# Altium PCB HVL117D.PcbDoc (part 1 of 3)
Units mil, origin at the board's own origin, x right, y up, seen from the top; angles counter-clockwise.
Board outline 2004.03 x 2004.03 mil, 6 copper layers (Top Layer, InternalPlane1, MidLayer1, InternalPlane2, MidLayer2, Bottom Layer), stack 60.56 mil thick; 218 components, 157 nets, 658 pads, 273 vias.
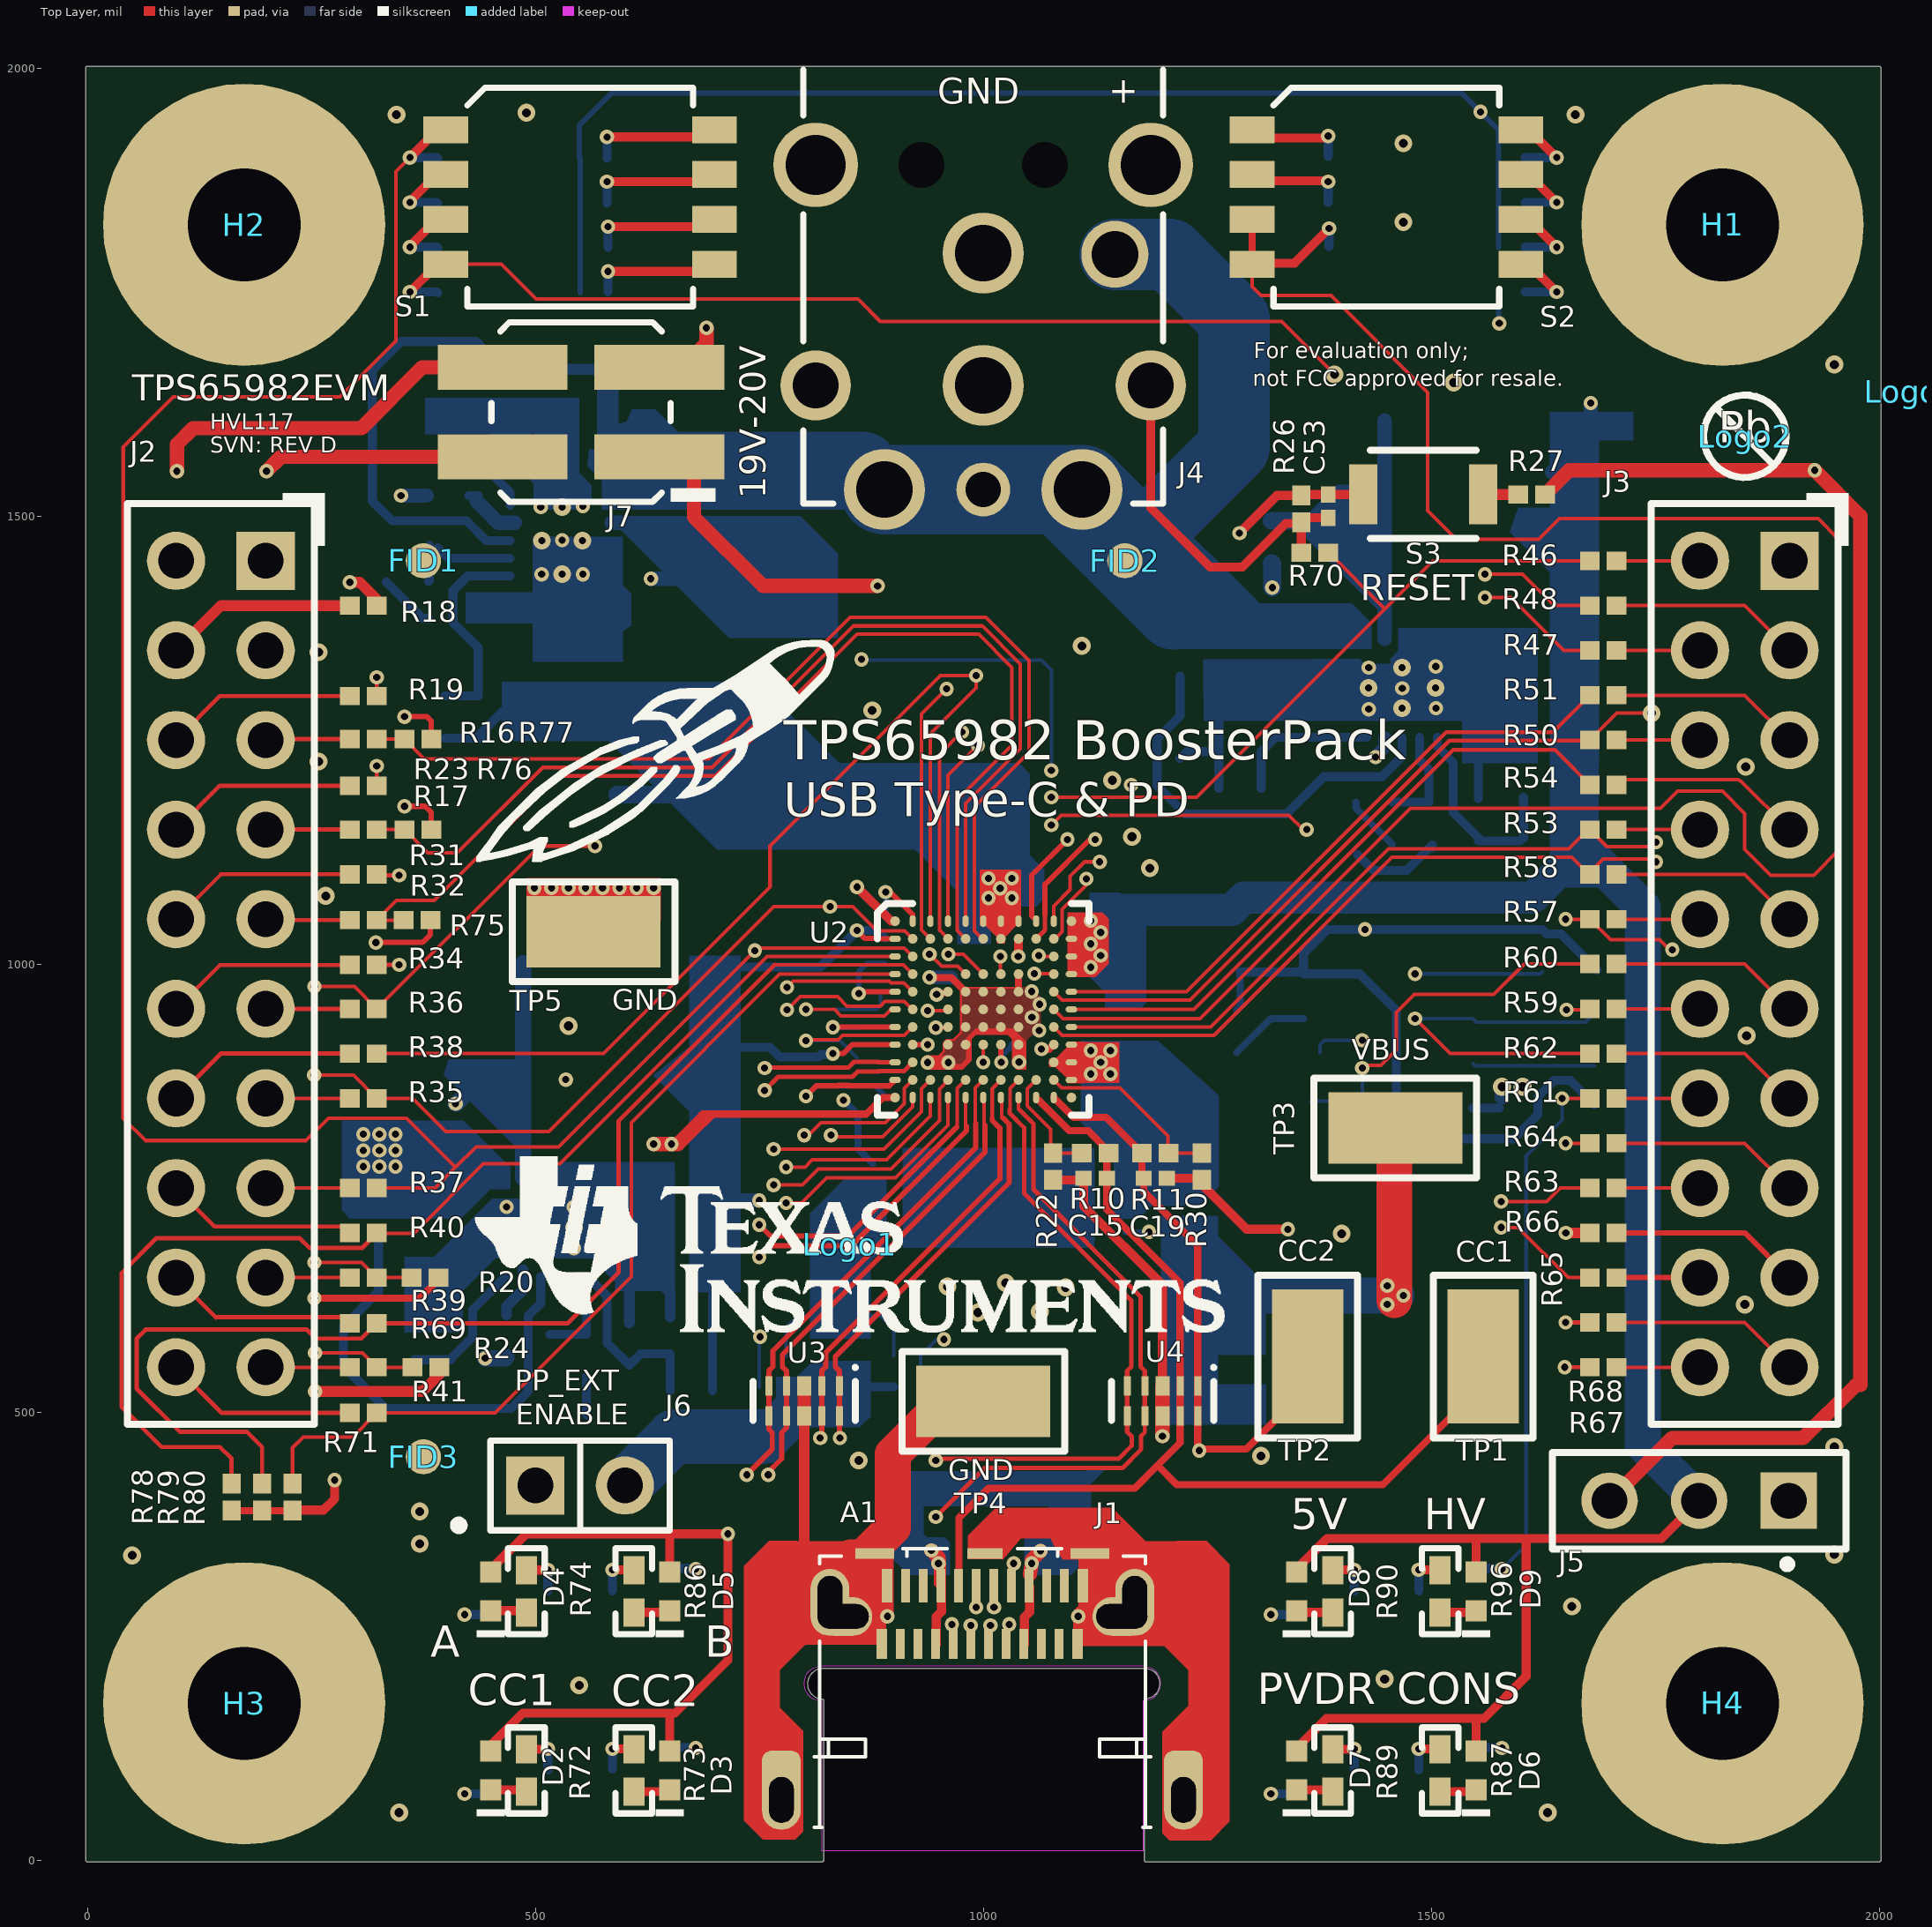
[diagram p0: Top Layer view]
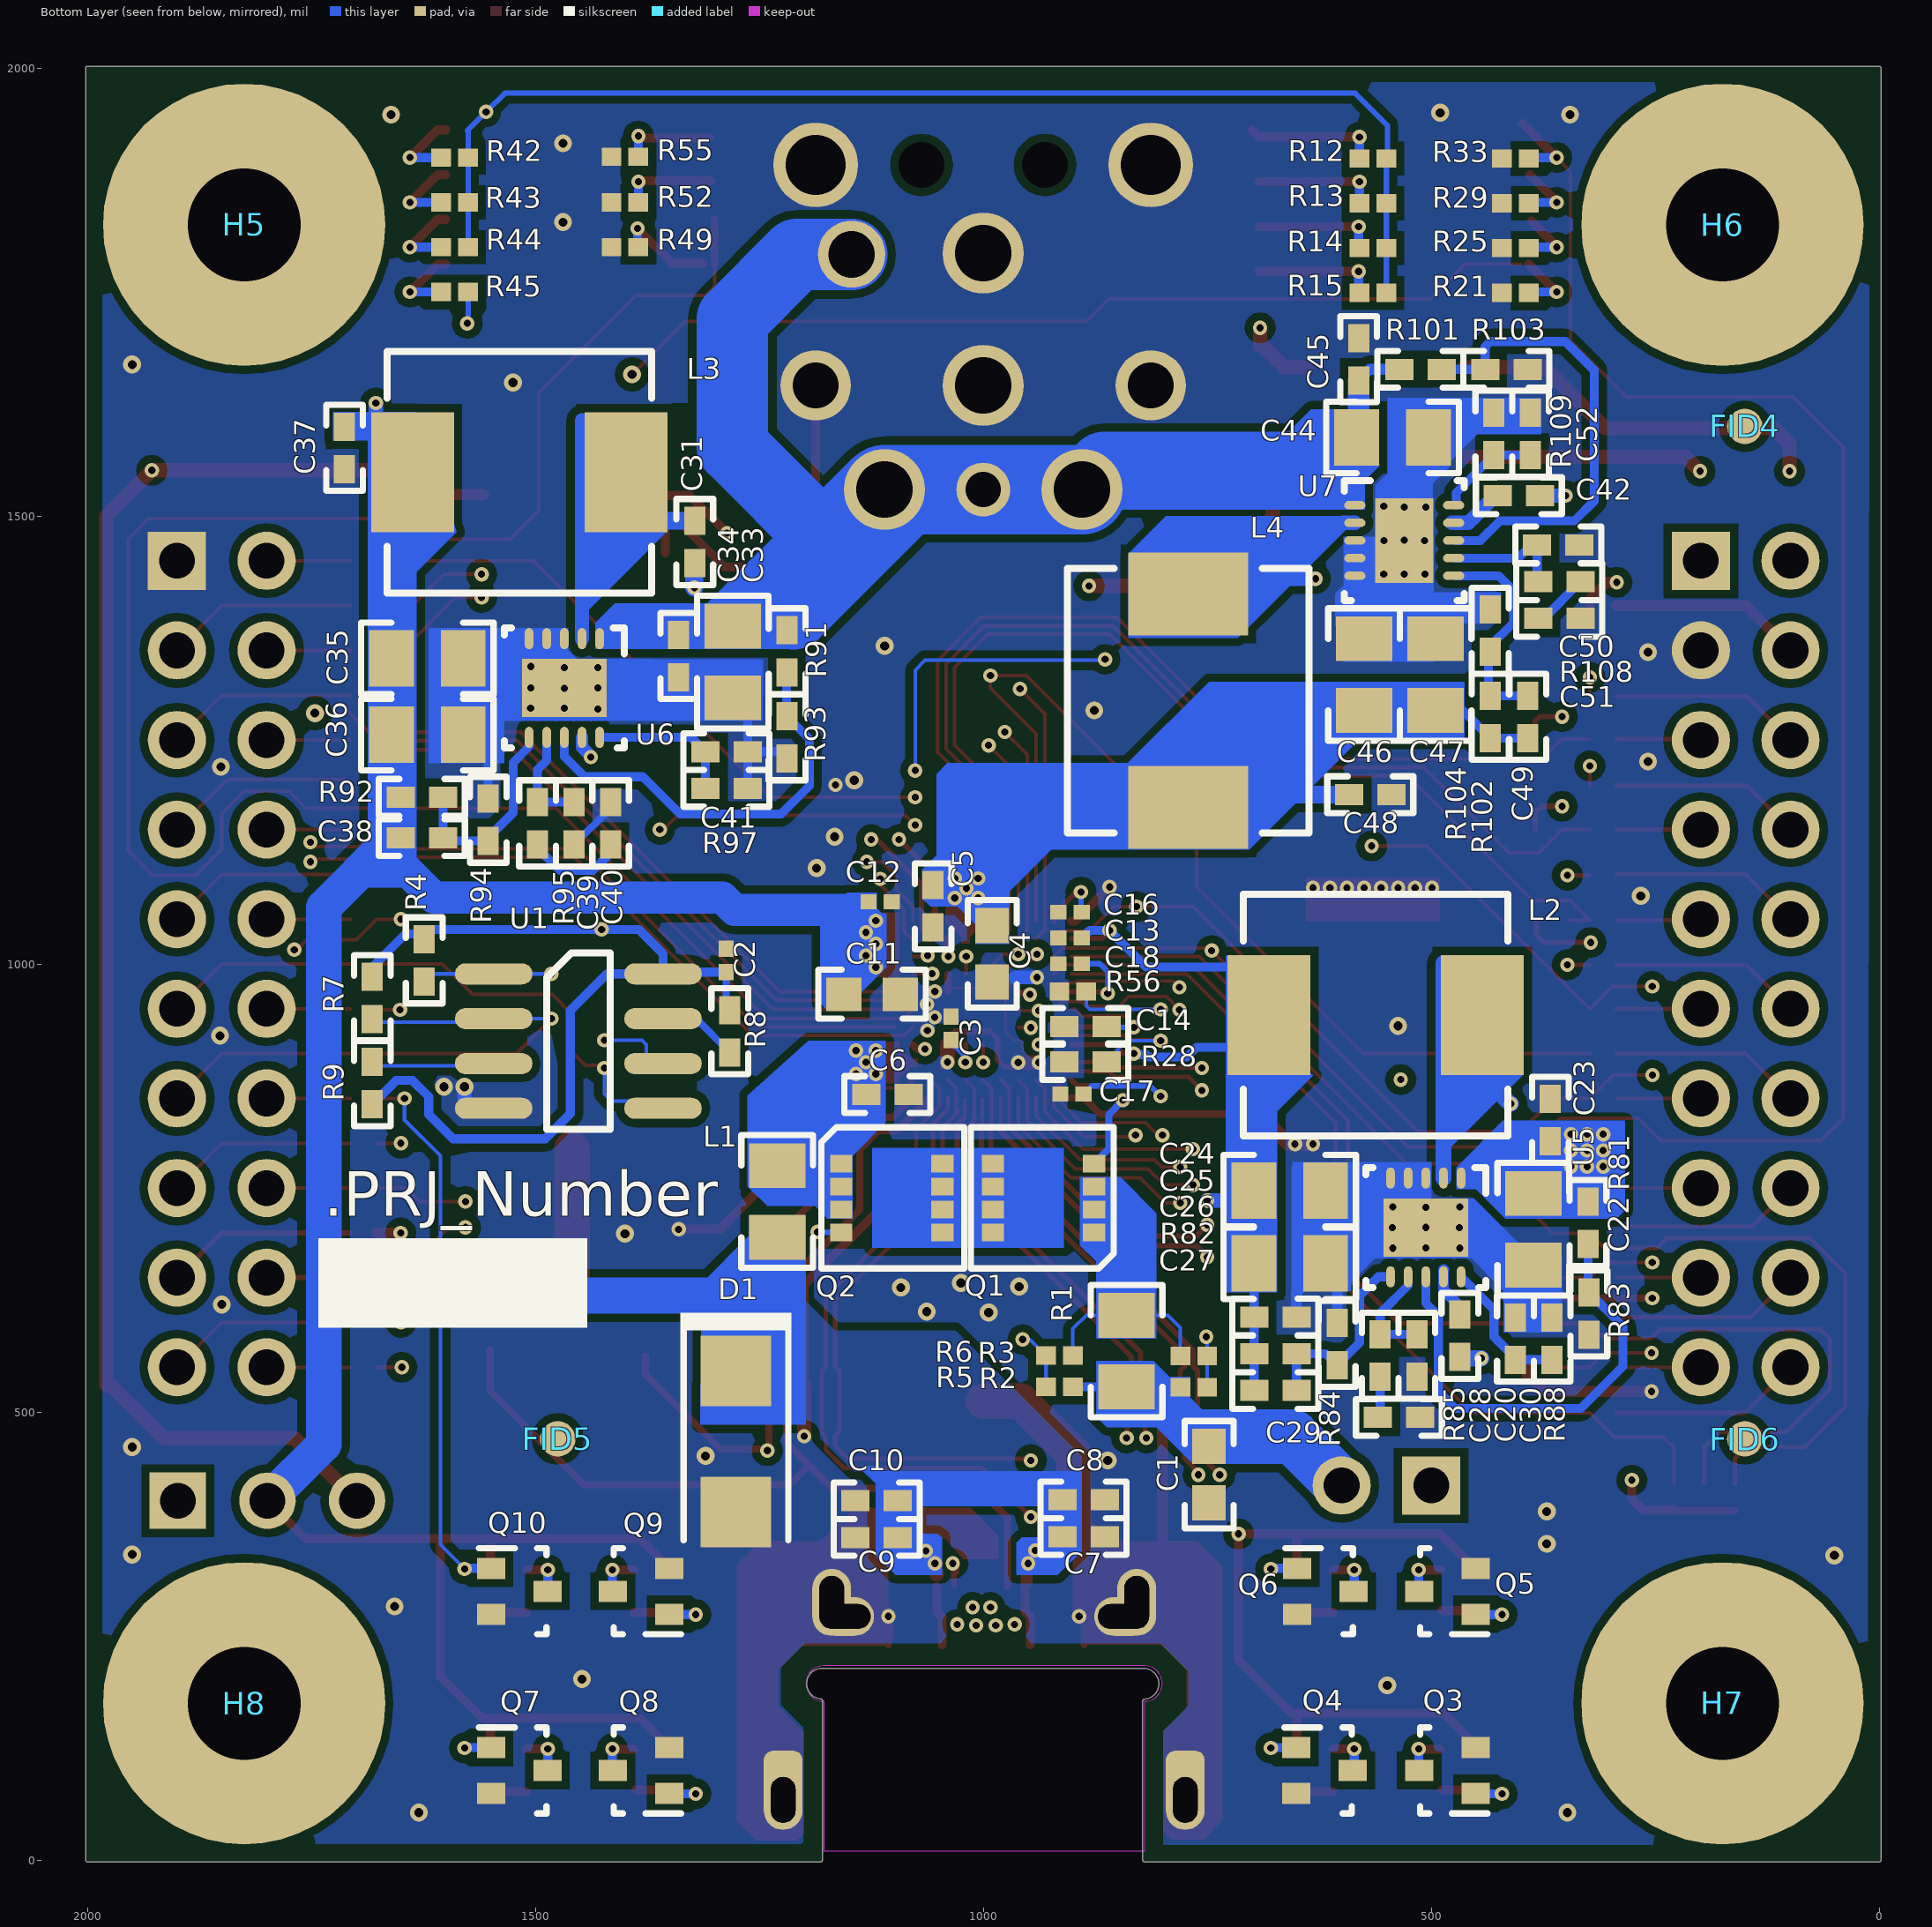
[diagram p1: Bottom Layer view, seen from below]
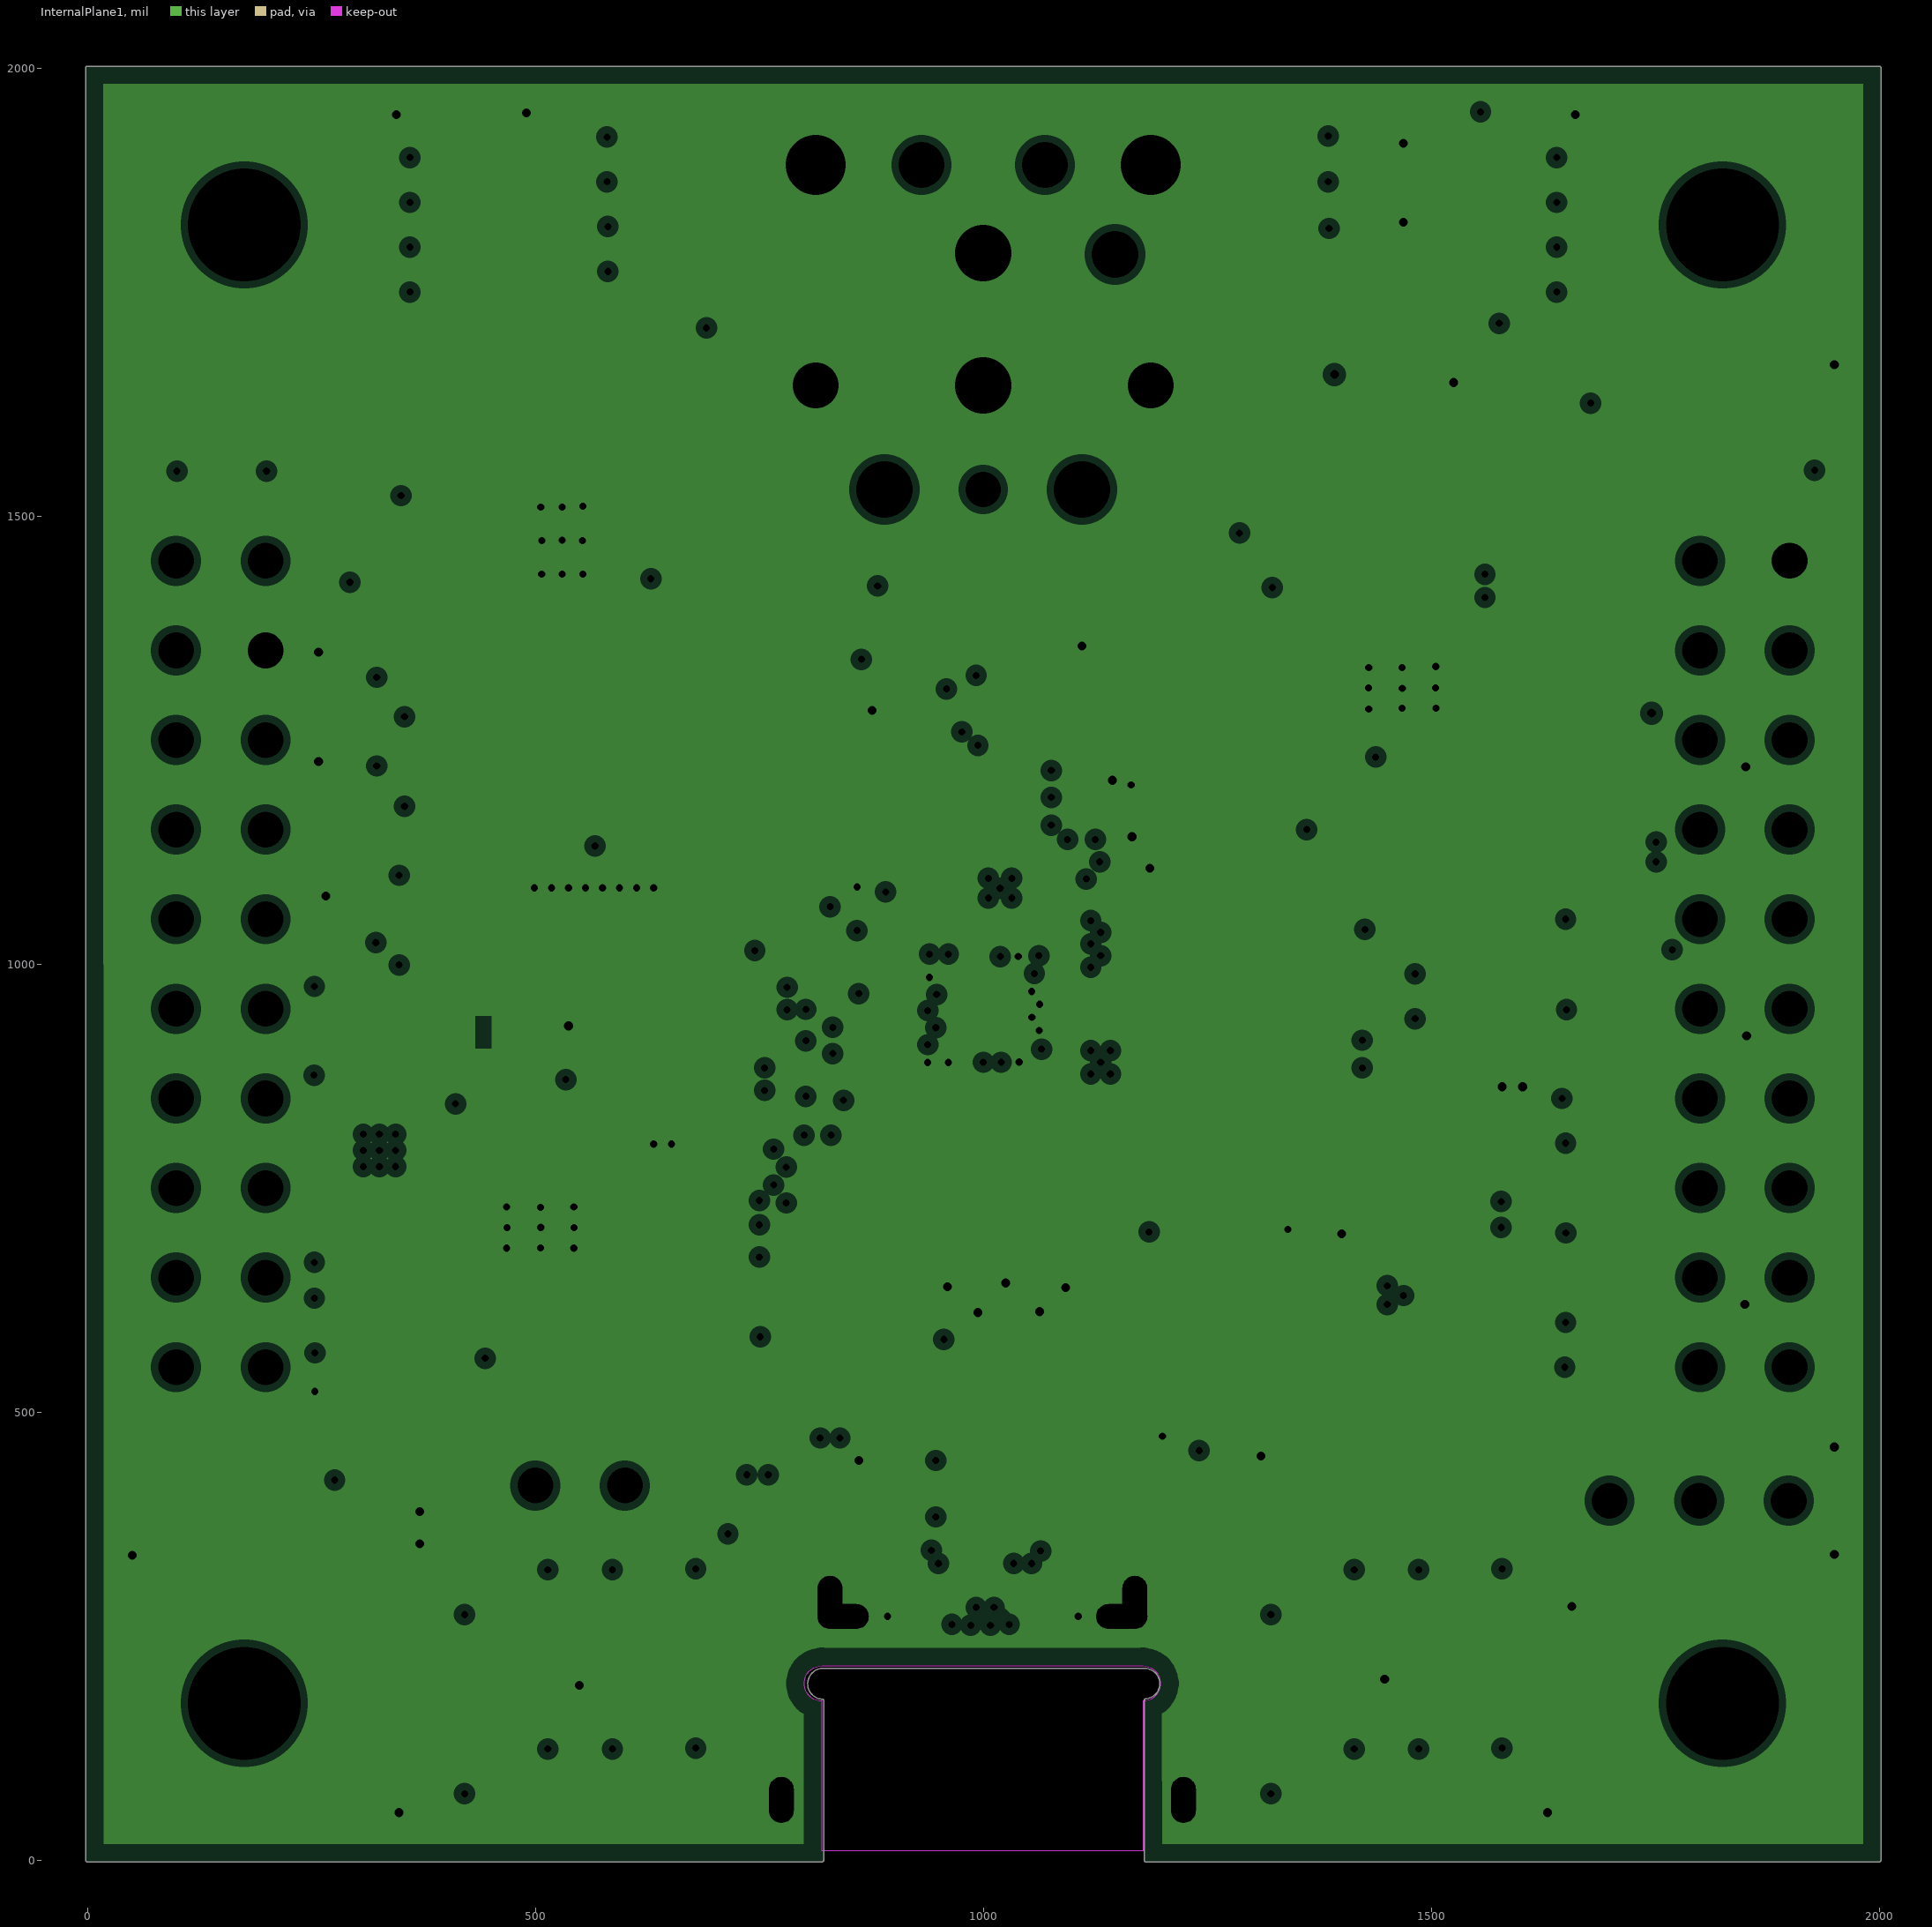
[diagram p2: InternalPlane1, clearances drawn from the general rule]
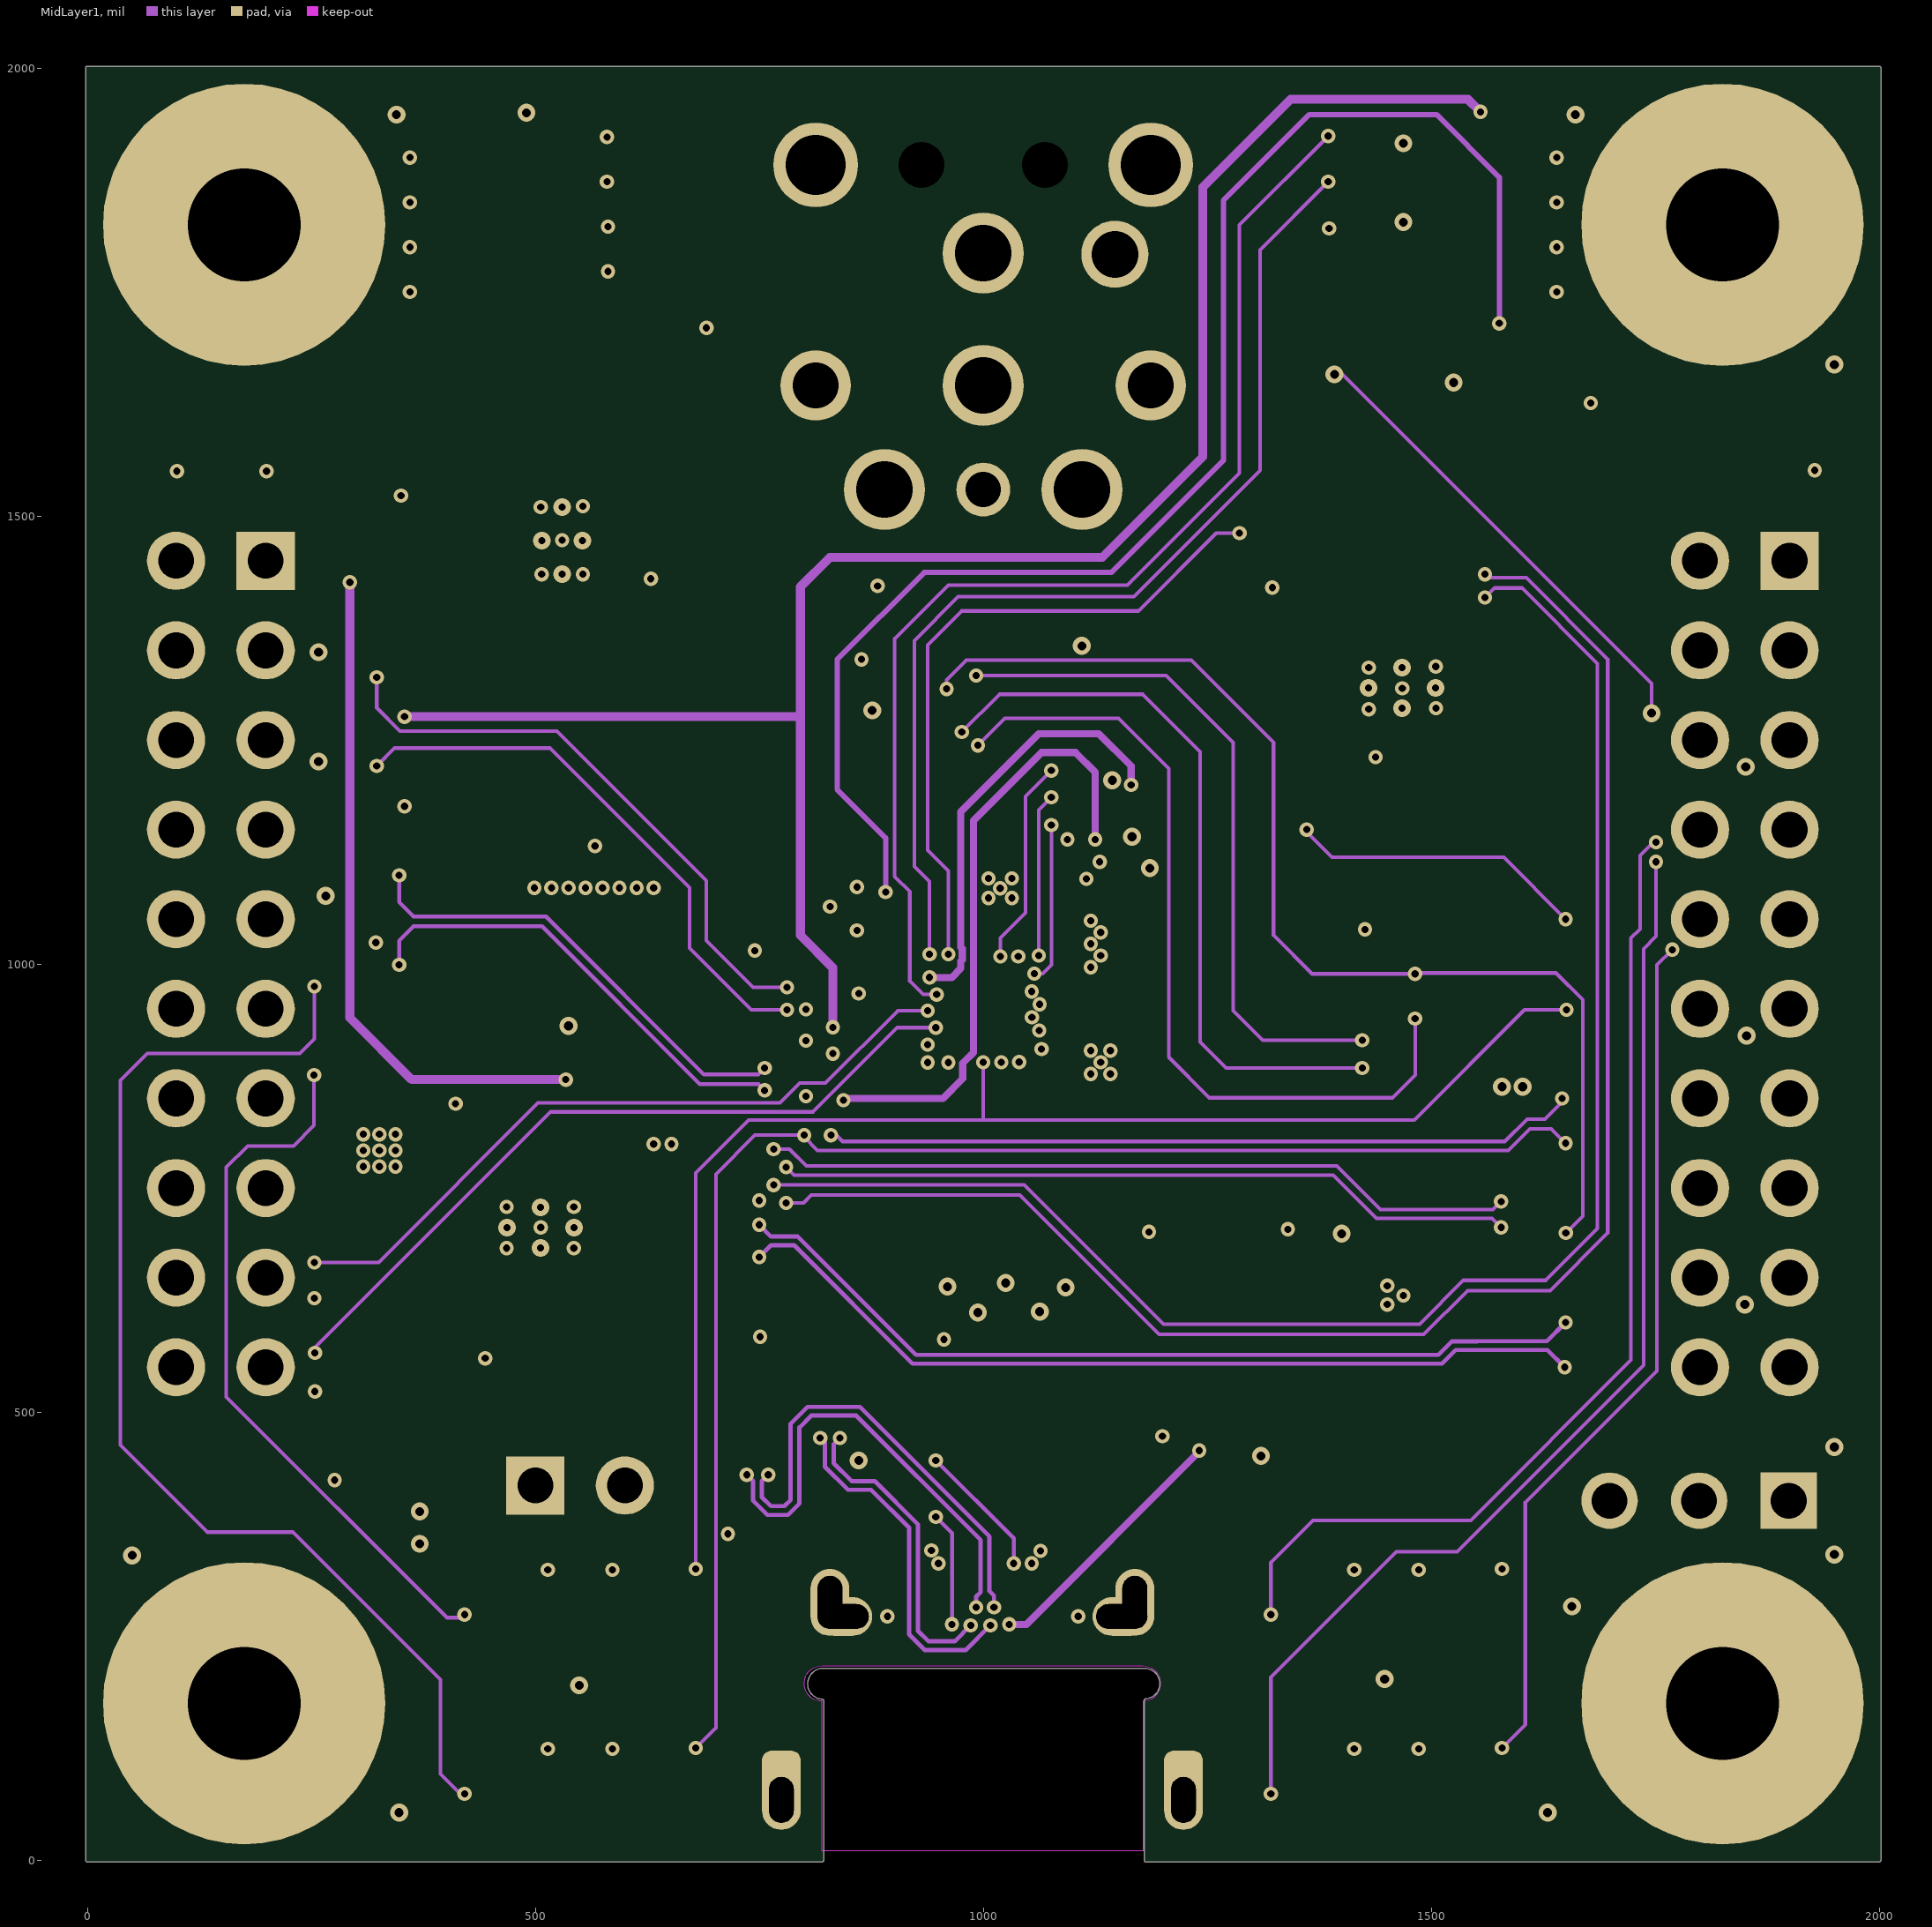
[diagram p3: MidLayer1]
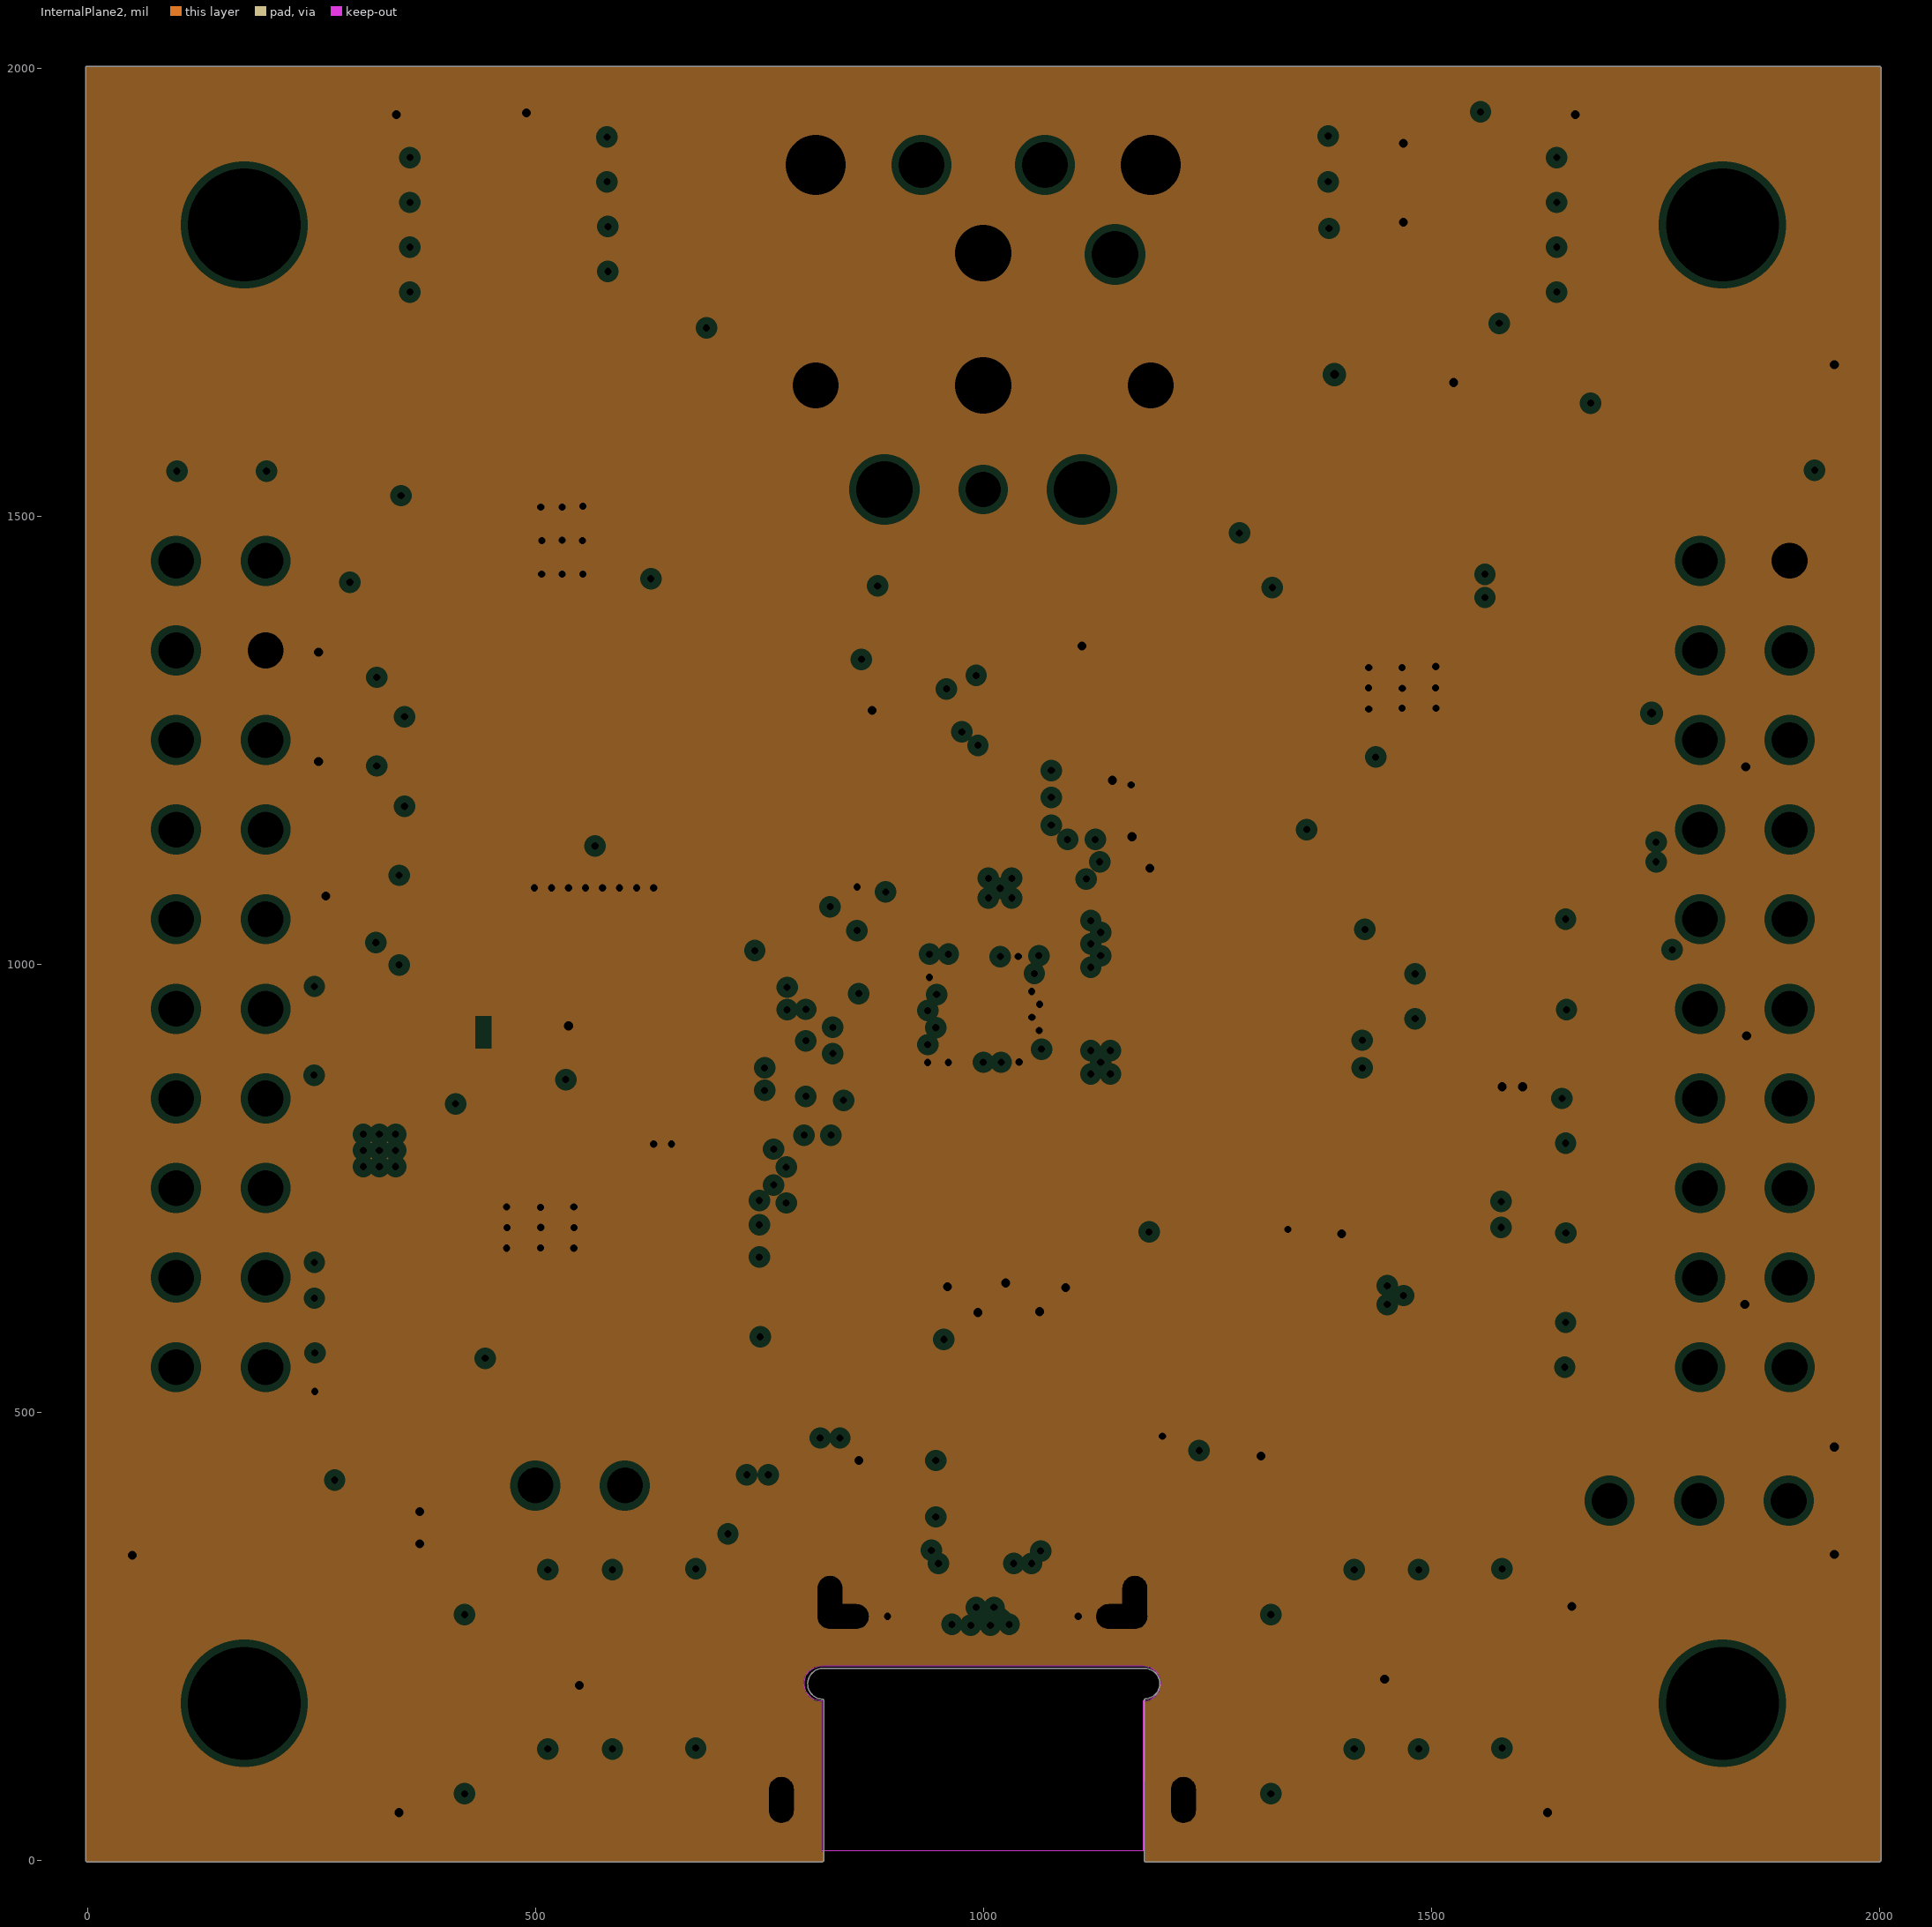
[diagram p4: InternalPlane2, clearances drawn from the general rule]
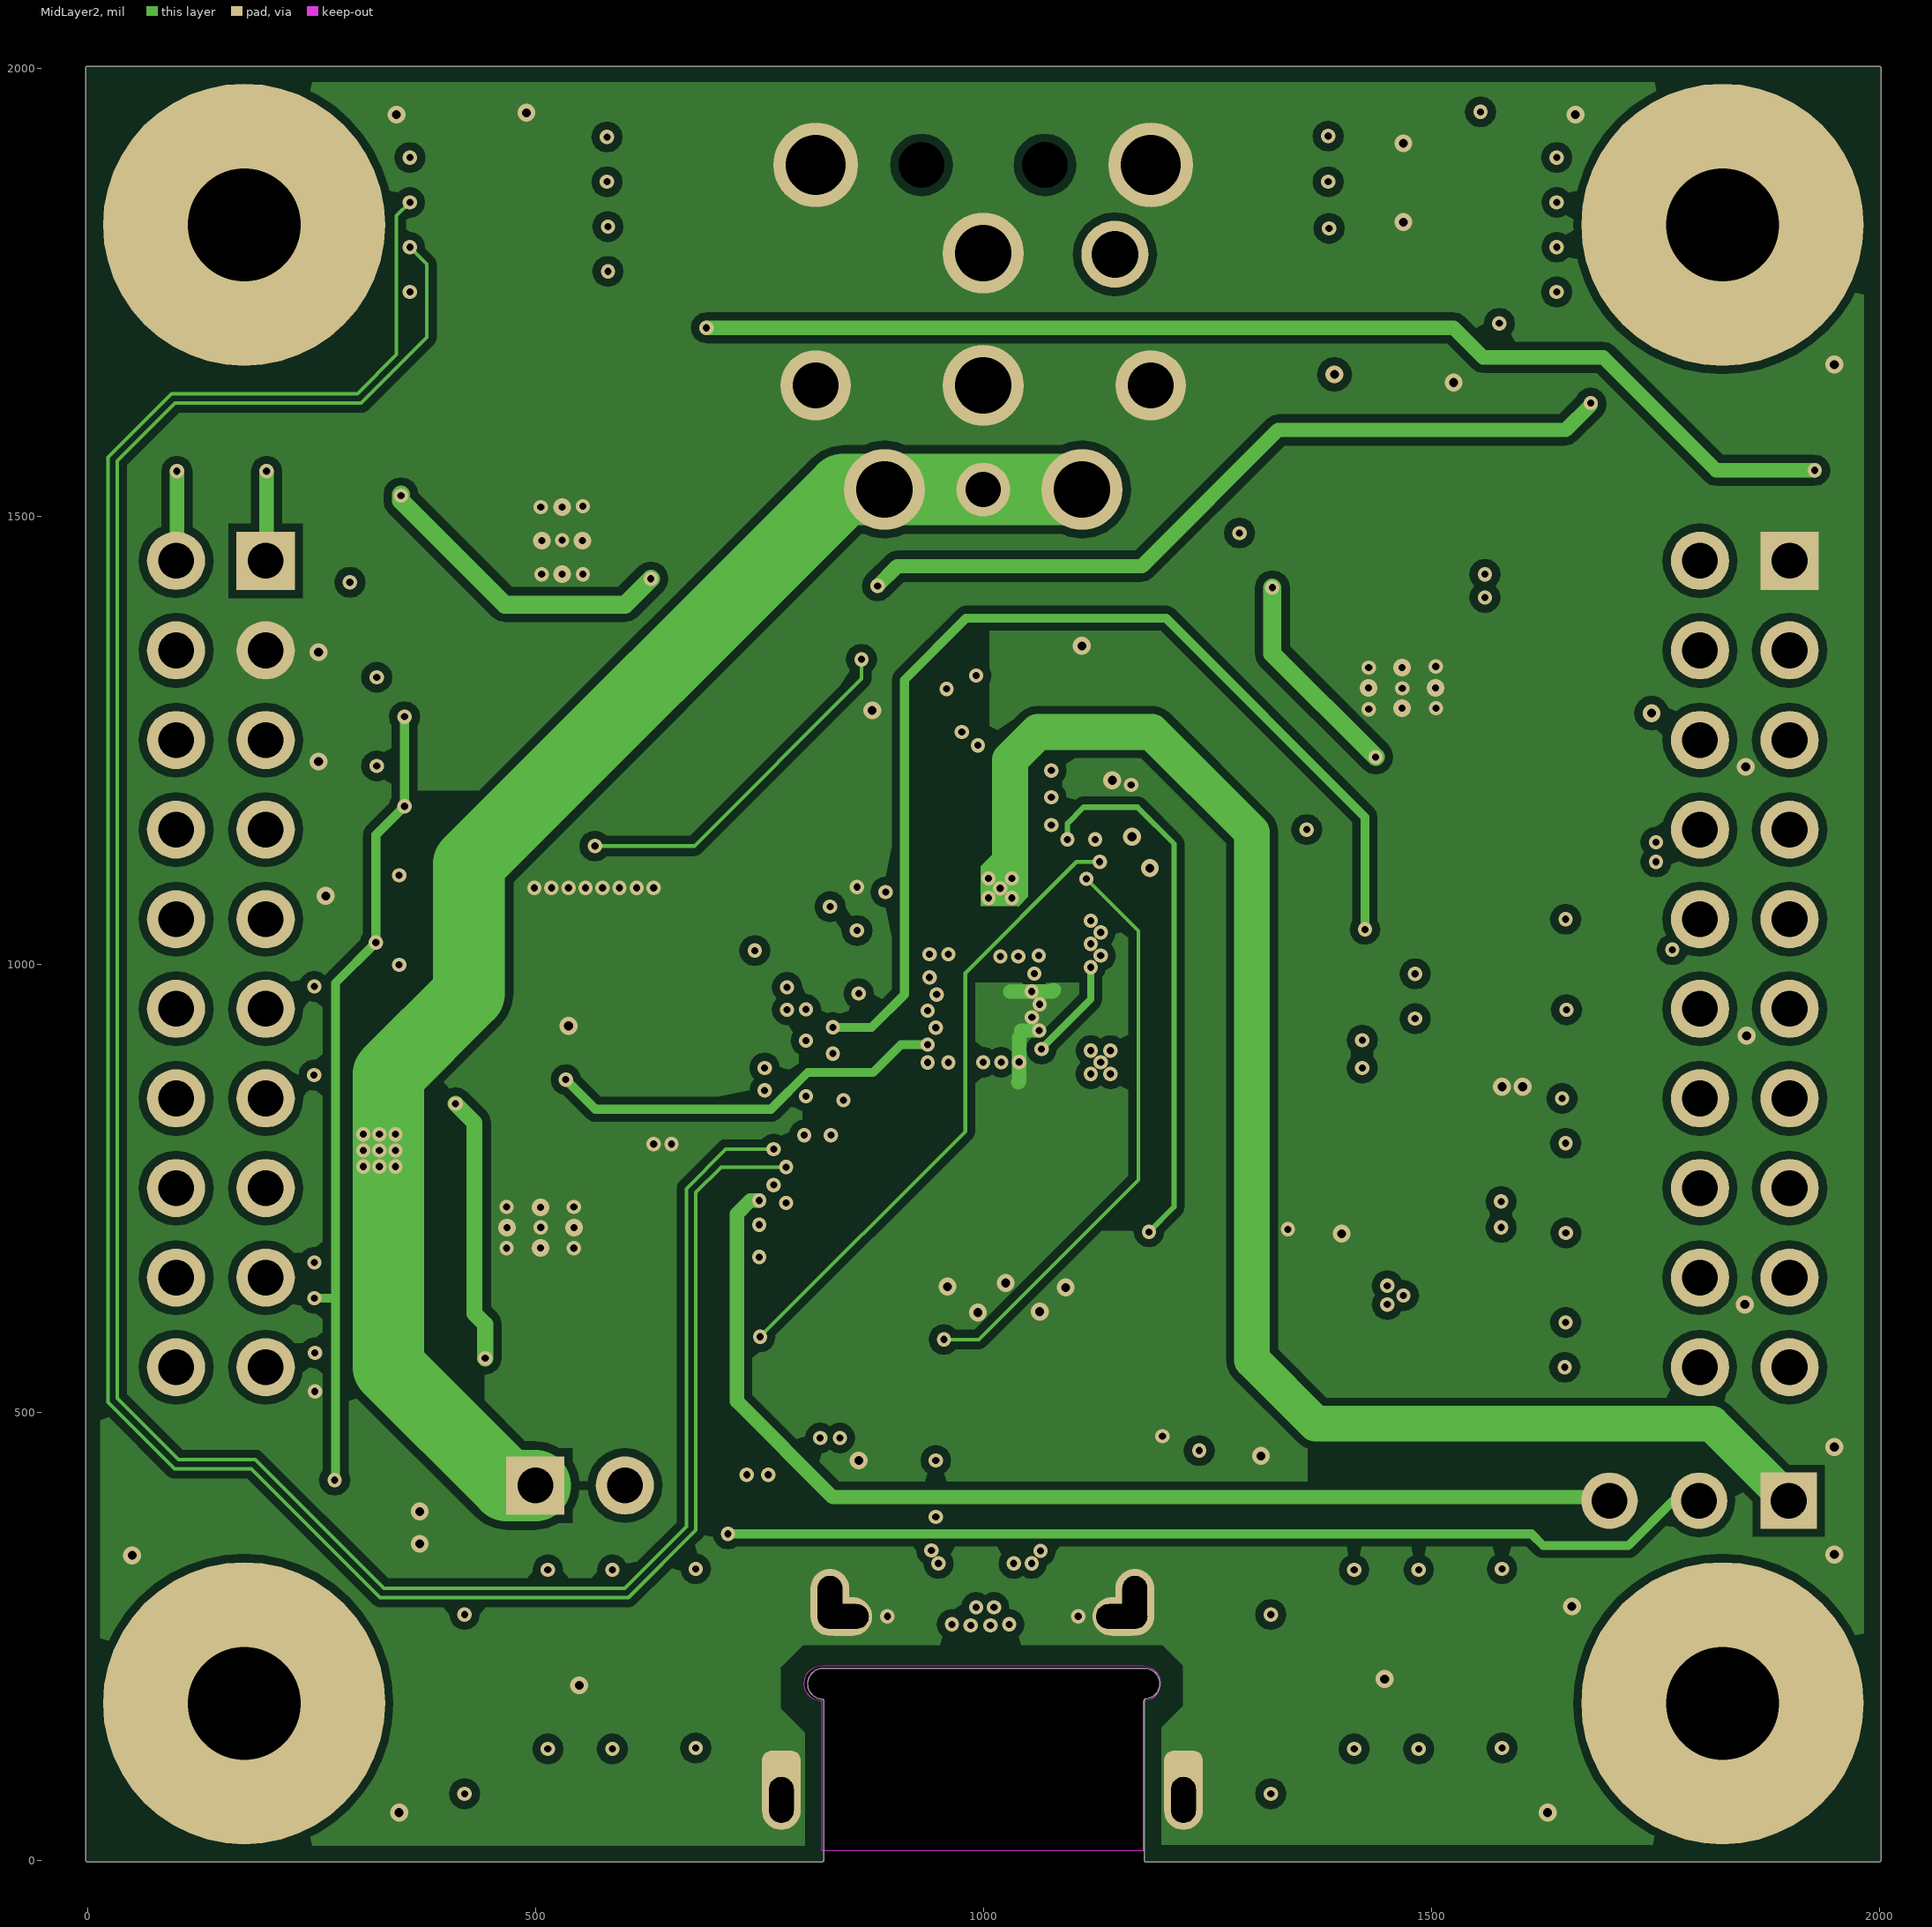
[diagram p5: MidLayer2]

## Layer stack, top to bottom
Top Layer: signal copper 1.4
Dielectric: core 5.91, FR-4, Dk 4.1
InternalPlane1: plane copper 1.4, net GND
Dielectric: prepreg 7.87, FR-4, Dk 4.1
MidLayer1: signal copper 1.4
Dielectric: core 24.6, FR-4, Dk 4.1
InternalPlane2: plane copper 1.4, net GND
Dielectric: prepreg 7.87, FR-4, Dk 4.1
MidLayer2: signal copper 1.4
Dielectric: core 5.91, FR-4, Dk 4.1
Bottom Layer: signal copper 1.4

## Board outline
0,-2.02 cw(c0,0) -2.01,0 -2.01,2000 cw(c0,2000) 0,2002.01 2000,2002.01 cw(c2000,2000) 2002.01,2000 2002.01,0 cw(c2000,0) 2000,-2.02 1181.57,-2.02 cw(c1181.57,0) 1179.56,0 1179.56,176.43 cw(c1181.57,176.43) 1179.7,177.16 cw(c1181.59,177.86) 1181.42,179.86 ccw(c1180,196.89) 1197.09,196.89 ccw(c1180,196.89) 1180,213.98 821.31,213.98 ccw(c821.31,216) 821.33,213.98 821.31,213.98 ccw(c821.31,196.68) 819.21,179.51 cw(c818.96,177.51) 819.48,179.46 cw(c820,177.51) 822.02,177.51 822.02,0 cw(c820,0) 820,-2.02

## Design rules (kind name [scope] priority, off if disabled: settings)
AcuteAngle [All] p1: minimum=4.50000000000000E+0001 checktracksonly=FALSE
AssemblyTestPointUsage [All] p1: valid=2
Clearance Clearance_BoardEdge_MountingHoles [OnCopper and InComponentClass('Mounting Holes') vs IsKeepOut] p1: gap=15
Clearance Clearance_BoardEdge_Poly [OnCopper and InPoly vs IsKeepOut] p2: gap=25
Clearance Clearance_BoardEdge [OnCopper and Not InComponentClass('Logo') and not InComponentClass('FiducialMark') and not InRegion(1000,500,4000,800) and Not IsKeepout vs IsKeepOut] p3: gap=5
Clearance Clearance_Poly [InPolygon] p4: gap=9
Clearance [All] p5: gap=3
ComponentClearance ComponentClearance_Shunt [InComponentClass('Header') vs InComponentClass('Shunt')] p1: gap=0 collisioncheckmode=3 verticalgap=0 showdistances=FALSE
ComponentClearance ComponentClearance_MountingHoles_FiducialMarks [InComponentClass('Mounting Holes') vs InComponentClass('FiducialMark')] p2: gap=50 collisioncheckmode=3 verticalgap=10 showdistances=FALSE
ComponentClearance ComponentClearance_Logo [InComponentClass('Logo')] p3: gap=0 collisioncheckmode=3 verticalgap=0 showdistances=FALSE
ComponentClearance ComponentClearance_ScrewToNut [(HasFootprint('NY PMS 440 0025 PH')) vs (HasFootprint('Keystone_1902C'))] p4: gap=5 collisioncheckmode=3 verticalgap=10 showdistances=FALSE
ComponentClearance ComponentClearance_MountingHoles [InComponentClass('Mounting Holes')] p5: gap=20 collisioncheckmode=3 verticalgap=100000 showdistances=FALSE
ComponentClearance ComponentClearance_SmallPassives [HasFootprint('0201*') or HasFootprint('0402*') or HasFootprint('0508') or HasFootprint('0603*') or HasFootprint('0612') or HasFootprint('0805*') or HasFootprint('0815*') or HasFootprint('0830*') or HasFootprint('1206*') or HasFootprint('1210*') or HasFootprint('1808*') or HasFootprint('1812*') or HasFootprint('1825*') or HasFootprint('2010*') or HasFootprint('2220*') or HasFootprint('2225*') or HasFootprint('2512*') or HasFootprint('2728*') or HasFootprint('3518*') vs HasFootprint('0201*') or HasFootprint('0402*') or HasFootprint('0508') or HasFootprint('0603*') or HasFootprint('0612') or HasFootprint('0805*') or HasFootprint('0815*') or HasFootprint('0830*') or HasFootprint('1206*') or HasFootprint('1210*') or HasFootprint('1808*') or HasFootprint('1812*') or HasFootprint('1825*') or HasFootprint('2010*') or HasFootprint('2220*') or HasFootprint('2225*') or HasFootprint('2512*') or HasFootprint('2728*') or HasFootprint('3518*')] p6: gap=15 collisioncheckmode=3 verticalgap=10 showdistances=FALSE
ComponentClearance ComponentClearance_THtoSMT [IsThruComponent vs IsSMTComponent] p7: gap=20 collisioncheckmode=3 verticalgap=30 showdistances=FALSE
ComponentClearance ComponentClearance_THtoTH [IsThruComponent vs IsThruComponent] p8: gap=10 collisioncheckmode=3 verticalgap=10 showdistances=FALSE
ComponentClearance [All] p9: gap=15 collisioncheckmode=3 verticalgap=10 showdistances=FALSE
DiffPairsRouting 100_DiffPair_DiffPairsRouting [InDifferentialPair ('C_SBU') Or InDifferentialPair ('AUX')] p1 off: maxlimit=6.5 minlimit=5 mostfreqgap=6.5 toplayer_maxgap=5.5 toplayer_prefgap=5.5 midlayer1_mingap=5.5 midlayer2_mingap=5.5 midlayer2_maxgap=5.5 midlayer2_prefgap=5.5 bottomlayer_mingap=5.5 bottomlayer_maxgap=5.5 bottomlayer_prefgap=5.5 maxuncoupledlength=500
DiffPairsRouting 90_DiffPair_DiffPairsRouting [InDifferentialPair ('C_USB_T') Or InDifferentialPair ('USB2_RP') Or InDifferentialPair ('C_USB_B')] p2 off: maxlimit=5 minlimit=3.5 mostfreqgap=5 toplayer_maxgap=4.75 toplayer_prefgap=4.75 midlayer1_mingap=5 midlayer2_mingap=5 bottomlayer_mingap=5 maxuncoupledlength=500
DiffPairsRouting [All] p3 off: maxlimit=100 minlimit=10 mostfreqgap=10 maxuncoupledlength=1000
FabricationTestPointUsage TestPointUsage [All] p1: valid=2 allowmultiple=FALSE
FabricationTestpoint Testpoint [All] p1: side=3 testpointundercomponent=TRUE minsize=40 maxsize=100 preferedsize=60 minholesize=0 maxholesize=40 preferedholesize=32 testpointgrid=1 allowsidetop=TRUE allowsidebottom=TRUE usegrid=TRUE gridtolerance=0.01
FanoutControl Fanout_LCC [IsLCC] p1: bgadir=Out bgaviamode=Centered fanoutstyle=Auto fanoutdirection=Alternating viagrid=1 // Fanout_LCC (Default Rule)
FanoutControl Fanout_BGA [IsBGA] p2: bgadir=Out bgaviamode=Centered fanoutstyle=Auto fanoutdirection=Alternating viagrid=1 // Fanout_BGA (Default Rule)
FanoutControl Fanout_Default [All] p4: bgadir=Out bgaviamode=Centered fanoutstyle=Auto fanoutdirection=Alternating viagrid=1 // Fanout_Default (Default Rule)
FanoutControl Fanout_Small [(CompPinCount < 5)] p5: bgadir=Out bgaviamode=Centered fanoutstyle=Auto fanoutdirection=OutThenIn viagrid=1 // Fanout_Small (Default Rule)
HoleSize [All] p1: absolutevalues=TRUE maxlimit=251 minlimit=6 maxpercent=80.000 minpercent=20.000
HoleToHoleClearance HoleToHoleClearance_Slot [HasSlotHole vs HasSlotHole] p1: gap=0 allowstackedmicrovias=TRUE
HoleToHoleClearance [All] p2: gap=5 allowstackedmicrovias=FALSE
MatchedLengths 100_DiffPair_MatchedLengths [InDifferentialPair ('C_SBU') Or InDifferentialPair ('AUX')] p1: tolerance=500 checknetsindiffpair=TRUE checkdiffpairvsdiffpair=FALSE checkothers=FALSE
MatchedLengths 90_DiffPair_MatchedLengths [InDifferentialPair ('C_USB_T') Or InDifferentialPair ('USB2_RP') Or InDifferentialPair ('C_USB_B')] p2: tolerance=500 checknetsindiffpair=TRUE checkdiffpairvsdiffpair=FALSE checkothers=FALSE
MinimumAnnularRing MinimumAnnularRing_ThermalPadVias [IsVia and InAnyComponent] p1: minimumring=5.91
MinimumAnnularRing [All] p2: minimumring=3
MinimumSolderMaskSliver MinimumSolderMaskSliver_Logo [InComponentClass('Logo') vs InComponentClass('Logo')] p1: minsoldermaskwidth=0.7
MinimumSolderMaskSliver [All] p2: minsoldermaskwidth=3
PlaneClearance [All] p1: clearance=8
PlaneConnect [All] p1: planeconnectstyle=Direct reliefexpansion=10 reliefentries=4 reliefconductorwidth=12 reliefairgap=4
PolygonConnect [All] p1: connectstyle=Direct reliefconductorwidth=10 reliefentries=4 polygonreliefangle="90 Angle" airgapwidth=10
RoutingVias ThermalPadVias [IsVia and InAnyComponent] p1: holewidth=7.87 width=19.68 viastyle="Through Hole" minholewidth=6 minwidth=12 maxholewidth=12.99 maxwidth=23.62
RoutingVias [All] p2: holewidth=16 width=34 viastyle="Through Hole" minholewidth=6 minwidth=12 maxholewidth=12 maxwidth=65
SMDToCorner [All] p1 off: distance=5000
SilkToSilkClearance SilkToSilkClearance_Pb-FreeLogo [(HasFootprint('Pb-Free_Overlay_Medium') OR HasFootprint('Pb-Free_Overlay_Small')) vs (HasFootprint('Pb-Free_Overlay_Medium') OR HasFootprint('Pb-Free_Overlay_Small'))] p1: silktosilkclearance=0
SilkToSilkClearance [All] p2: silktosilkclearance=0.25
SilkscreenOverComponentPads [IsPad] p1: minsilkscreentomaskgap=1
SolderMaskExpansion [All] p1: expansion=1.97
Width 100_DiffPair_Width [InDifferentialPair('C_SBU') Or InDifferentialPair('AUX')] p1: maxlimit=5 minlimit=4 preferedwidth=4.4 toplayer_prefwidth=5 midlayer1_maxwidth=4.4 minimp=50.000000 maximp=50.000000 favimp=50.000000
Width 90_DiffPair_Width [InDifferentialPair('C_USB_T') Or InDifferentialPair('USB2_RP') Or InDifferentialPair('C_USB_B')] p2: maxlimit=5.8 minlimit=4 preferedwidth=5.8 midlayer1_maxwidth=4.8 midlayer1_prefwidth=4.8 midlayer2_maxwidth=4.8 midlayer2_prefwidth=4.8 minimp=50.000000 maximp=50.000000 favimp=50.000000
Width [All] p3: maxlimit=100 minlimit=4 preferedwidth=10 checkconnectedcopper=TRUE
12 further rules are at their usual default settings.

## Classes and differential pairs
component class Header: J6 J7
component class AssemblyNote: ZZ2 ZZ3 ZZ4
component class FiducialMark: FID1 FID2 FID3 FID4 FID5 FID6
component class HVL117D_Hardware_ANSI-B: FID1 FID2 FID3 FID4 FID5 FID6 H1 H2 H3 H4 H5 H6 H7 H8 Logo1 Logo2 Logo3 ZZ2 ZZ3 ZZ4
component class Logo: Logo1
component class "Mounting Holes": H1 H2 H3 H4
component class HVL117D_Power_Delivery: C1 C2 C3 C4 C5 C6 C7 C8 C9 C10 C11 C12 C13 C14 C15 C16 C17 C18 C19 C53 D1 D2 D3 D4 D5 D6 D7 D8 D9 J1 J2 J3 J6 L1 Q1 Q2 Q3 Q4 Q5 Q6 Q7 Q8 Q9 Q10 R1 R2 R3 R4 R5 R6 R7 R8 R9 R10 R11 R12 R13 R14 R15 R16 R17 R18 R19 R20 R21 R22 R23 R24 R25 R26 R28 R29 R30 R31 R32 R33 R34 R35 R36 R37 R38 R39 R40 R41 R42 R43 R44 R45 R46 R47 R48 R49 R50 R51 R52 R53 R54 R55 R56 R57 R58 R59 R60 R61 R62 R63 R64 R65 R66 R67 R68 R69 R70 R71 R72 R73 R74 R75 R76 R77 R78 R79 R80 R86 R87 R89 R90 R96 S1 S2 TP1 TP2 TP3 TP4 U1 U2 U3 U4
component class HVL117D_Power_Path: C20 C22 C23 C24 C25 C26 C27 C28 C29 C30 C31 C33 C34 C35 C36 C37 C38 C39 C40 C41 C42 C44 C45 C46 C47 C48 C49 C50 C51 C52 J4 J5 J7 L2 L3 L4 R27 R81 R82 R83 R84 R85 R88 R91 R92 R93 R94 R95 R97 R101 R102 R103 R104 R108 R109 S3 TP5 U5 U6 U7
differential pair AUX: +AUX_P -AUX_N
differential pair C_SBU: +C_SBU_P -C_SBU_N
differential pair C_USB_B: +C_USB_B_P -C_USB_B_N
differential pair C_USB_T: +C_USB_T_P -C_USB_T_N
differential pair USB2_RP: +USB2_RP_P -USB2_RP_N

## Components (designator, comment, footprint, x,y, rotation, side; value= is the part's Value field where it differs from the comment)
C1 "GRM188R61E106MA73" 0603 748,430 r270 bottom
C2 "CL03A104KP3NNNC" 0201#1 1287,1004 r90 bottom
C3 "GRM033R60J224ME90" 0201#1 1036,928.37 r90 bottom
C4 "GRM188R61E106MA73" 0603 990,1011.37 r270 bottom
C5 "C1005X7R1H104M" 0402 1056,1064.37 r270 bottom
C6 "C1005JB1V105K050BC" 0402 1107,854.37 r180 bottom
C7 "GRM155R71H103KA88D" 0402 888,361 r180 bottom
C8 "GRM155R71H103KA88D" 0402 888,402 r180 bottom
C9 "GRM155R71H103KA88D" 0402 1119,360 r0 bottom
C10 "GRM155R71H103KA88D" 0402 1119,401 r0 bottom
C11 "GRM188R61A226ME15D" 0603_100 1124,966.37 r180 bottom
C12 "CL03A104KP3NNNC" 0201#1 1115,1069.37 r180 bottom
C13 "CL03A105MP3NSNC" 0201#1 903,1029 r0 bottom
C14 "CL05A106MP5NUNC" 0402 886,930.37 r0 bottom
C15 "GRM033R71E221KA01D" 0201#2 1125.01,761 r180 top
C16 "CL03A105MP3NSNC" 0201#1 903,1058 r0 bottom
C17 "CL03A105MP3NSNC" 0201#1 901,855 r0 bottom
C18 "CL03A105MP3NSNC" 0201#1 903,1000.37 r0 bottom
C19 "GRM033R71E221KA01D" 0201#1 1192,761 r0 top
C20 "C1005X7R1H104M" 0402 468,585 r270 bottom
C22 "C2012X5R1E106K125AB" 0805_HV 386,704 r270 bottom
C23 "C1005X7R1H104M" 0402 367,826 r90 bottom
C24 "C2012X5R1V226M125AC" 0805_HV 658,747 r180 bottom
C25 "C2012X5R1V226M125AC" 0805_HV 658,666 r180 bottom
C26 "C1005X7R1H104M" 0402 674,606 r180 bottom
C27 "GRM1555C1H121JA01D" 0402 674,524 r180 bottom
C28 "C1005C0G1H331J" 0402 516,563 r270 bottom
C29 "GRM155R71H562KA88D" 0402 536,494 r180 bottom
C30 "GRM1555C1H121JA01D" 0402 406,582 r90 bottom
C31 "C1005X7R1H104M" 0402 1322,1471 r90 bottom
C33 "C2012X5R1E106K125AB" 0805_HV 1279.6,1337 r270 bottom
C34 "C1005X7R1H104M" 0402 1340,1343.7 r270 bottom
C35 "C2012X5R1V226M125AC" 0805_HV 1620.6,1341 r180 bottom
C36 "C2012X5R1V226M125AC" 0805_HV 1620.6,1256 r180 bottom
C37 "C1005X7R1H104M" 0402 1713,1576 r270 bottom
C38 "GRM1555C1H121JA01D" 0402 1626.6,1141 r180 bottom
C39 "CC0402KRX7R9BB101" 0402 1456.6,1157 r270 bottom
C40 "GRM155R61H222KA01D" 0402 1416,1157 r90 bottom
C41 "GRM1555C1H121JA01D" 0402 1286.6,1237 r180 bottom
C42 "C1005X7R1H104M" 0402 402.12,1522.69 r180 bottom
C44 "C2012X5R1E106K125AB" 0805_HV 543.12,1587.69 r180 bottom
C45 "C1005X7R1H104M" 0402 581,1675 r90 bottom
C46 "C2012X5R1V226M125AC" 0805_HV 575,1323 r90 bottom
C47 "C2012X5R1V226M125AC" 0805_HV 495,1323 r90 bottom
C48 "C1005X7R1H104M" 0402 568,1189 r180 bottom
C49 "GRM1555C1H121JA01D" 0402 392.12,1275.91 r90 bottom
C50 "GRM1555C1H910JA01D" 0402 358.12,1467.69 r180 bottom
C51 "GRM155R71H182KA01D" 0402 357.12,1385.69 r180 bottom
C52 "GRM1555C1H121JA01D" 0402 389.12,1591.69 r90 bottom
C53 "GRM033R61A103KA01D" 0201#1 1385,1511 r270 top
D1 "B340A-13-F" SMA 1276,467 r270 bottom
D2 "LW QH8G-Q2S2-3K5L-1" "LW QH8G_White" 450,100 r270 top
D3 "LW QH8G-Q2S2-3K5L-1" "LW QH8G_White" 650,100 r270 top
D4 "LW QH8G-Q2S2-3K5L-1" "LW QH8G_White" 450,300 r270 top
D5 "LW QH8G-Q2S2-3K5L-1" "LW QH8G_White" 650,300 r270 top
D6 "LW QH8G-Q2S2-3K5L-1" "LW QH8G_White" 1550,100 r270 top
D7 "LW QH8G-Q2S2-3K5L-1" "LW QH8G_White" 1350,100 r270 top
D8 "LW QH8G-Q2S2-3K5L-1" "LW QH8G_White" 1350,300 r270 top
D9 "LW QH8G-Q2S2-3K5L-1" "LW QH8G_White" 1550,300 r270 top
FID1 "Fiducial" Fiducial10-20 375,1450 r0 top
FID2 "Fiducial" Fiducial10-20 1158,1450 r0 top
FID3 "Fiducial" Fiducial10-20 375,450 r0 top
FID4 "Fiducial" Fiducial10-20 150,1600 r180 bottom
FID5 "Fiducial" Fiducial10-20 1475,470 r180 bottom
FID6 "Fiducial" Fiducial10-20 150,470 r180 bottom
H1 "NY PMS 440 0025 PH" "NY PMS 440 0025 PH" 1825,1825 r0 top locked
H2 "NY PMS 440 0025 PH" "NY PMS 440 0025 PH" 175,1825 r0 top locked
H3 "NY PMS 440 0025 PH" "NY PMS 440 0025 PH" 175,175 r0 top locked
H4 "NY PMS 440 0025 PH" "NY PMS 440 0025 PH" 1825,175 r0 top locked
H5 "1902C" Keystone_1902C 1825,1825 r180 bottom locked
H6 "1902C" Keystone_1902C 175,1825 r180 bottom locked
H7 "1902C" Keystone_1902C 175,175 r180 bottom locked
H8 "1902C" Keystone_1902C 1825,175 r180 bottom locked
J1 "20-0000016-01" Lintes_20-0000016-01 999,10 r0 top
J2 "PPPC102LFBN-RC" Sullins_PPPC102LFBN-RC 149,1000 r90 top
J3 "PPPC102LFBN-RC" Sullins_PPPC102LFBN-RC 1850,1000 r90 top
J4 "JPD1135-509-7F" CONN_JPD1135-509 1000,2000 r180 top
J5 "PPPC031LFBN-RC" Sullins_PPPC031LFBN-RC 1799,401 r180 top
J6 "90120-0122" CONN_90120-0122 550,418 r0 top
J7 "15-91-2040" Molex_15-91-2040 551,1616 r90 top
L1 "FBMJ2125HM210NT" 0805_HV 1230,735 r270 bottom
L2 "ASPI-0630LR-100M-T15" ASPI-0630LR 562,943 r0 bottom
L3 "ASPI-0630LR-100M-T15" ASPI-0630LR 1518,1549 r0 bottom
L4 "ASPI-0630LR-100M-T15" ASPI-0630LR 771,1294 r270 bottom
Logo1 "Texas Instruments" TI_Stacked_Overlay_Small 851,687 r0 top
Logo2 "Pb-Free Symbol" Pb-Free_Overlay_Small 1850,1589 r0 top
Logo3 "FCC disclaimer" FCC_disclaimer_stacked 2036,1639 r0 top
Q1 "CSD17309Q3" TRANS_NexFET_Q3 935,739 r0 bottom
Q2 "CSD17309Q3" TRANS_NexFET_Q3 1100,739 r180 bottom
Q3 "DTC114EUAT106" SOT-323 482,100 r0 bottom
Q4 "DTC114EUAT106" SOT-323 619,100 r180 bottom
Q5 "DTC114EUAT106" SOT-323 482,300 r0 bottom
Q6 "DTC114EUAT106" SOT-323 618,300 r180 bottom
Q7 "DTC114EUAT106" SOT-323 1518,100 r180 bottom
Q8 "DTC114EUAT106" SOT-323 1382,100 r0 bottom
Q9 "DTC114EUAT106" SOT-323 1382,300 r0 bottom
Q10 "DTC114EUAT106" SOT-323 1518,300 r180 bottom
R1 "WSL0805R0100FEA18" 0805_HV 840,568 r90 bottom
R2 "ERJ-1GE0R00C" 0201M 765,527.5 r0 bottom
R3 "ERJ-1GE0R00C" 0201M 765,562.5 r0 bottom
R4 "CRCW04023K30JNED" 0402 1624,1004 r270 bottom
R5 "ERJ-1GE0R00C" 0201M 915,528 r180 bottom
R6 "ERJ-1GE0R00C" 0201M 915,563 r180 bottom
R7 "CRCW04023K30JNED" 0402 1682,962 r270 bottom
R8 "CRCW04023K30JNED" 0402 1283,925 r270 bottom
R9 "CRCW04023K30JNED" 0402 1682,867 r270 bottom
R10 "ERJ-1GE0R00C" 0201M 1125.01,789 r0 top
R11 "ERJ-1GE0R00C" 0201M 1192,789 r180 top
R12 "CRCW02011K00FKED" 0201M 565,1899 r180 bottom
R13 "CRCW02011K00FKED" 0201M 565,1849 r180 bottom
R14 "CRCW02011K00FKED" 0201M 565,1799 r180 bottom
R15 "CRCW02011K00FKED" 0201M 565,1749 r180 bottom
R16 "ERJ-1GE0R00C" 0201M 308,1251 r180 top
R17 "ERJ-1GE0R00C" 0201M 308,1150 r180 top
R18 "ERJ-1GE0R00C" 0201M 308,1400 r180 top
R19 "ERJ-1GE0R00C" 0201M 308,1299 r180 top
R20 "CRCW02013K83FKED" 0201M 377,650 r0 top
R21 "CRCW0201100KFKED" 0201M 406,1749 r0 bottom
R22 "ERJ-1GE0R00C" 0201M 1078,774 r270 top
R23 "ERJ-1GE0R00C" 0201M 308,1199 r0 top
R24 "CRCW0201100KFKED" 0201M 378,550 r0 top
R25 "CRCW0201100KFKED" 0201M 406,1799 r0 bottom
R26 "CRCW0201100KFKED" 0201M 1355,1508 r90 top
R27 "CRCW02011K00FKED" 0201M 1612,1524 r0 top
R28 "CRCW040215K0FKED" 0402 886,891 r180 bottom
R29 "CRCW0201100KFKED" 0201M 406,1849 r0 bottom
R30 "ERJ-1GE0R00C" 0201M 1244,774 r270 top
R31 "ERJ-1GE0R00C" 0201M 308,1100 r0 top
R32 "ERJ-1GE0R00C" 0201M 308,1049 r180 top
R33 "CRCW0201100KFKED" 0201M 406,1899 r0 bottom
R34 "ERJ-1GE0R00C" 0201M 308,999 r0 top
R35 "ERJ-1GE0R00C" 0201M 308,850 r180 top
R36 "ERJ-1GE0R00C" 0201M 308,950 r180 top
R37 "ERJ-1GE0R00C" 0201M 308,750 r180 top
R38 "ERJ-1GE0R00C" 0201M 308,900 r0 top
R39 "ERJ-1GE0R00C" 0201M 308,650 r180 top
R40 "ERJ-1GE0R00C" 0201M 308,700 r0 top
R41 "ERJ-1GE0R00C" 0201M 308,550 r180 top
R42 "CRCW02011K00FKED" 0201M 1590,1900 r180 bottom
R43 "CRCW02011K00FKED" 0201M 1590,1850 r180 bottom
R44 "CRCW02011K00FKED" 0201M 1590,1800 r180 bottom
R45 "CRCW02011K00FKED" 0201M 1590,1750 r180 bottom
R46 "ERJ-1GE0R00C" 0201M 1692,1450 r180 top
R47 "ERJ-1GE0R00C" 0201M 1692,1350 r180 top
R48 "ERJ-1GE0R00C" 0201M 1692,1400 r180 top
R49 "CRCW0201100KFKED" 0201M 1400,1800 r0 bottom
R50 "ERJ-1GE0R00C" 0201M 1692,1250 r180 top
R51 "ERJ-1GE0R00C" 0201M 1692,1300 r0 top
R52 "CRCW0201100KFKED" 0201M 1400,1850 r0 bottom
R53 "ERJ-1GE0R00C" 0201M 1692,1150 r0 top
R54 "ERJ-1GE0R00C" 0201M 1692,1200 r0 top
R55 "CRCW0201100KFKED" 0201M 1400,1901 r0 bottom
R56 "ERJ-1GE0R00C" 0201M 900,969.37 r180 bottom
R57 "ERJ-1GE0R00C" 0201M 1692,1050 r0 top
R58 "ERJ-1GE0R00C" 0201M 1692,1100 r0 top
R59 "ERJ-1GE0R00C" 0201M 1692,950 r0 top
R60 "ERJ-1GE0R00C" 0201M 1692,1000 r0 top
R61 "ERJ-1GE0R00C" 0201M 1692,850 r0 top
R62 "ERJ-1GE0R00C" 0201M 1692,900 r0 top
R63 "ERJ-1GE0R00C" 0201M 1692,750 r0 top
R64 "ERJ-1GE0R00C" 0201M 1692,800 r0 top
R65 "ERJ-1GE0R00C" 0201M 1692,650 r0 top
R66 "ERJ-1GE0R00C" 0201M 1692,700 r180 top
R67 "ERJ-1GE0R00C" 0201M 1692,550 r180 top
R68 "ERJ-1GE0R00C" 0201M 1692,600 r180 top
R69 "ERJ-1GE0R00C" 0201M 308,599 r0 top
R70 "CRCW0201100KFKED" 0201M 1370,1459 r0 top
R71 "ERJ-1GE0R00C" 0201M 308,499 r0 top
R72 "CRCW0402560RJNED" 0402 490,100 r270 top
R73 "CRCW0402560RJNED" 0402 610,100 r270 top
R74 "CRCW0402560RJNED" 0402 490,300 r270 top
R75 "CRCW02013K83FKED" 0201M 368,1049 r0 top
R76 "CRCW02013K83FKED" 0201M 369,1150 r0 top
R77 "CRCW02019K09FKED" 0201M 369,1251 r0 top
R78 "CRCW02019K09FKED" 0201M 161,404.96 r270 top
R79 "CRCW02013K83FKED" 0201M 195,404.96 r270 top
R80 "CRCW02013K83FKED" 0201M 229,404.96 r270 top
R81 "CRCW0402220KJNED" 0402 325,711 r90 bottom
R82 "CRCW0402100KFKED" 0402 674,565 r0 bottom
R83 "CRCW040243K2FKED" 0402 324,610 r90 bottom
R84 "CRCW040232K4FKED" 0402 605,576 r270 bottom
R85 "CRCW04022K74FKED" 0402 557,563 r90 bottom
R86 "CRCW0402560RJNED" 0402 610,300 r270 top
R87 "CRCW0402560RJNED" 0402 1510,100 r270 top
R88 "CRCW040247K5FKED" 0402 365,582 r270 bottom
R89 "CRCW0402560RJNED" 0402 1390,100 r270 top
R90 "CRCW0402560RJNED" 0402 1390,300 r270 top
R91 "CRCW0402220KJNED" 0402 1219,1349 r90 bottom
R92 "CRCW0402100KFKED" 0402 1626.6,1186 r0 bottom
R93 "CRCW040243K2FKED" 0402 1219,1253 r90 bottom
R94 "CRCW040219K1FKED" 0402 1552.6,1161 r270 bottom
R95 "CRCW04028K45FKED" 0402 1497.6,1157 r90 bottom
R96 "CRCW0402560RJNED" 0402 1510,300 r270 top
R97 "CRCW040247K5FKED" 0402 1286.6,1196 r0 bottom
R101 "CRCW0402220KJNED" 0402 512.12,1663.69 r0 bottom
R102 "CRCW0402100KFKED" 0402 434.12,1275.91 r270 bottom
R103 "CRCW040243K2FKED" 0402 416.12,1663.69 r0 bottom
R104 "CRCW04027K15FKED" 0402 434.12,1371.91 r270 bottom
R108 "CRCW04029K53FKED" 0402 357.12,1426.69 r0 bottom
R109 "CRCW040247K5FKED" 0402 430.12,1591.69 r270 bottom
S1 "TDA04H0SB1" SW_TDA04H0SB1 550,1856 r0 top
S2 "TDA04H0SB1" SW_TDA04H0SB1 1450,1856 r0 top
S3 "B3U-1000P" SW_B3U-1000P 1491,1524 r0 top
TP1 "TESTPOINT" Keystone_5019 1558,562 r90 top
TP2 "TESTPOINT" Keystone_5019 1362,562 r90 top
TP3 "TESTPOINT" Keystone_5019 1460,817 r0 top
TP4 "TESTPOINT" Keystone_5019 1000,512 r0 top
TP5 "TESTPOINT" Keystone_5019 565,1036 r0 top
U1 "W25Q80DVSNIG" SOIC-8 1452,914 r180 bottom
U2 "TPS65982AAZQZR" ZQZ0096A_Oval 1000,949.37 r0 top
U3 "TPD4E05U06DQA" DQA0010A 800,512.37 r270 top
U4 "TPD4E05U06DQA" DQA0010A 1200,512.37 r270 top
U5 "TPS54335DRCR" DRC0010J 506,706 r270 bottom
U6 "TPS54335DRCR" DRC0010J 1467.6,1308 r270 bottom
U7 "TPS54335DRCR" DRC0010J 530.12,1472.69 r180 bottom
ZZ2 "These assemblies are ESD sensitive, ESD precautions shall be observed." AssemblyNote 185,3829.11 r0 top
ZZ3 "These assemblies must be clean and free from flux and all contaminants. Use of no clean flux is not acceptable." AssemblyNote 185,3740.56 r0 top
ZZ4 "These assemblies must comply with workmanship standards IPC-A-610 Class 2, unless otherwise specified." AssemblyNote 185,3652 r0 top

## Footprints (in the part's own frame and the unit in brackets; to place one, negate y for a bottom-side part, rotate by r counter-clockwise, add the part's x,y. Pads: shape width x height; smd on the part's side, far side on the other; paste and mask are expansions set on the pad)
0201#1 [mm] "Data from Kemet datasheet CC101_COM dated 7/28/11"
  rect 0.46x0.42 smd mask+0.048: 1(-0.33,0) 2(0.33,0)
  body extent -0.31,-0.16 0.31,0.16, height 0.26
0201#2 [mm] "Data from Kemet datasheet CC101_COM dated 7/28/11"
  rect 0.46x0.42 smd mask+0: 1(-0.33,0) 2(0.33,0)
  body extent -0.31,-0.16 0.31,0.16, height 0.26
0201M [mm] "Data from Kemet datasheet CC101_COM dated 7/28/11"
  rect 0.56x0.52 smd mask+0.048: 1(-0.38,0) 2(0.38,0)
  body extent -0.31,-0.16 0.31,0.16, height 0.26
0402 [mm] "0402 from SM-752 data"
  rect 0.8x0.6 smd: 1(-0.6,0) 2(0.6,0)
  silkscreen extent -1.22,-0.52 1.22,0.52, body extent -0.55,-0.3 0.55,0.3, height 0.6
0603 [mm] "0603 from SM-752 data"
  rect 1x0.95 smd: 1(-0.8,0) 2(0.8,0)
  silkscreen extent -1.52,-0.69 1.52,0.69, body extent -0.87,-0.47 0.87,0.47, height 0.85
0603_100 [mm] "SMD, 2-Leads, Body 1.6x0.8mm"
  rect 1x0.95 smd: 1(-0.8,0) 2(0.8,0)
  silkscreen extent -1.52,-0.69 1.52,0.69, body extent -0.87,-0.47 0.87,0.47, height 1
0805_HV [mil] "0805 with 30mil clearance between pads"
  rect 50x63 smd: 1(-40,0) 2(40,0)
  silkscreen extent -74,-40 74,40, body extent -43,-29 43,29, height 43
ASPI-0630LR [mm] "SMD, 2-Leads, Body 7.2x6.65mm"
  rect 2.35x3.4 smd: 1(-3.025,0) 2(3.025,0)
  silkscreen extent -3.75,-3.42 3.75,3.42, body extent -3.75,-3.42 3.75,3.42, height 3
AssemblyNote [mil] "Assembly Note"
CONN_90120-0122 [mm] "Molex"
  rect 1.65x1.65 hole 1.016 mask+0: 1(-1.27,0)
  round 1.65 hole 1.016 mask+0: 2(1.27,0)
  silkscreen extent -3.56,-1.27 2.54,1.27, body extent -2.54,-1.27 2.54,1.27, height 9.29
CONN_JPD1135-509 [mm] "Foxconn recommended land pattern"
  round 1.524 hole 1: 1(0,11.95)
  round 2.3 hole 1.6: 2(-2.8,11.95) 3(2.8,11.95) 4(0,9) 5(0,5.25)
  round 2 hole 1.3: 6(-4.75,9) 7(4.75,9)
  round 2.4 hole 1.7: 8(-4.75,2.75) 9(4.75,2.75)
  round 0 hole 1.3 unplated: 10(-1.75,2.75) 11(1.75,2.75)
  silkscreen extent -5.1,0.05 5.1,12.35, body extent -5,0 5,12.3, height 11
DQA0010A [mm] "SON, 10-Leads, Body 1x2.5mm, Pitch 0.5mm, TI Recommended"
  rect 0.55x0.2 smd: 1(-0.425,1) 2(-0.425,0.5) 4(-0.425,-0.5) 5(-0.425,-1) 6(0.425,-1) 7(0.425,-0.5) 9(0.425,0.5) 10(0.425,1)
  rect 0.55x0.4 smd: 3(-0.425,0) 8(0.425,0)
  silkscreen extent -1,-1.45 0.55,1.5, body extent -0.55,-1.3 0.55,1.3, height 0.56
DRC0010J [mm] "SON, 10-Leads, Body 3x3mm, Pitch 0.5mm, Thermal Pad 2.4x1.65mm, TI Recommended"
  oval 0.6x0.24 smd: 1(-1.4,1) 2(-1.4,0.5) 3(-1.4,0) 4(-1.4,-0.5) 5(-1.4,-1) 6(1.4,-1) 7(1.4,-0.5) 8(1.4,0) 9(1.4,0.5) 10(1.4,1)
  rect 1.65x2.4 smd paste-0.825: 11(0,0)
  Top Layer region: 0.135,1.5 0.365,1.5 0.365,1.1 0.135,1.1
  Top Layer region: -0.135,1.1 -0.365,1.1 -0.365,1.5 -0.135,1.5
  Top Layer region: -0.135,-1.5 -0.365,-1.5 -0.365,-1.1 -0.135,-1.1
  Top Layer region: 0.135,-1.1 0.365,-1.1 0.365,-1.5 0.135,-1.5
  silkscreen extent -1.7,-1.7 1.7,1.7, body extent -1.55,-1.55 1.55,1.55, height 1.01
FCC_disclaimer_stacked [mil]
Fiducial10-20 [mm]
  round 1 smd mask+0.5: 1(0,0)
Keystone_1902C [mil] "Hex Standoff, 4-40 threaded, nylon"
  body extent -145,-126 146,126, height 501
Keystone_5019 [mm] "Test Point, Miniature, SMT"
  rect 3.8x2.03 smd: 1(0,0)
  silkscreen extent -2.31,-1.42 2.31,1.42, body extent -1.9,-1.02 1.9,1.02, height 2.29
Lintes_20-0000016-01 [mm] "Connector, Receptacle, USB Type C, SMT"
  rect 1.1x0.3 smd: 1(3.05,8.44) 3(-3.05,8.44)
  rect 1x0.3 smd: 2(0.07,8.44)
  rect 0.3x0.95 smd: A1(-2.7,7.525) A12(2.85,7.525)
  rect 0.25x0.95 smd: A2(-2.175,7.525) A3(-1.675,7.525) A4(-1.175,7.525) A5(-0.675,7.525) A6(-0.175,7.525) A7(0.325,7.525) A8(0.825,7.525) A9(1.325,7.525) A10(1.825,7.525) A11(2.325,7.525)
  rect 0.3x0.85 smd: B1(2.7,5.875) B12(-2.85,5.875)
  rect 0.25x0.85 smd: B2(2.175,5.875) B3(1.675,5.875) B4(1.175,5.875) B5(0.675,5.875) B6(0.175,5.875) B7(-0.325,5.875) B8(-0.825,5.875) B9(-1.325,5.875) B10(-1.825,5.875) B11(-2.325,5.875)
  oval 1.1x1.9 hole 0.7 slot 1.5 at 90 deg: H1(4.323,7.05) H3(-4.323,7.05)
  oval 1.65x1.1 hole 0.7 slot 1.45 at 0 deg: H2(3.949,6.65) H4(-3.949,6.65)
  oval 1.1x1.7 hole 0.7 slot 1.3 at 90 deg: H5(5.7,1.45) H7(-5.7,1.45)
  rrect50% 1.1x1.7 all layers, no hole: H6(5.7,2) H8(-5.7,2)
  Keep-Out Layer board cut-out: -4.55,0 -4.55,4.25 -4.767,4.3 -4.941,4.438 -5.037,4.639 -5.037,4.861 -4.941,5.062 -4.767,5.2 -4.55,5.25 -4.55,5.25 -4.55,5.25 4.55,5.25 4.55,5.25 4.767,5.2 4.941,5.062 5.037,4.861 5.037,4.639 4.941,4.438 4.767,4.3 4.55,4.25 4.55,4.25 4.55,0
  silkscreen extent -4.77,0.68 4.77,8.58, body extent -5.8,-1.56 5.8,8.59, height 2.44
"LW QH8G_White" [mm] "SMD, 2-Leads, Body 1x0.5mm"
  rect 0.6x0.6 smd paste-0.3: 1(-0.55,0) 2(0.55,0)
  silkscreen extent 1.1,-0.4 1.3,0.4, body extent -0.55,-0.3 0.55,0.3, height 0.4
Molex_15-91-2040 [mil] "Molex"
  rect 50x144.88 smd: 1(-50,-87.5) 2(-50,87.5) 3(50,-87.5) 4(50,87.5)
  silkscreen extent -100,-150 100,100, body extent -100,-137 100,138, height 380
"NY PMS 440 0025 PH" [mm] "4-40 nylon screw and mounting hole"
  round 8 hole 3.2: 1(0,0)
  body extent -3.3,-3.3 3.3,3.3, height 2.69
Pb-Free_Overlay_Small [mil]
  silkscreen extent -46,-46 46,46
SMA [mm] "Molded Diode, 2-Leads, Body 4.3x2.6mm, IPC Medium Density, based on OnSemi component dimensions and land pattern"
  rect 2x2 smd: 1(-2,0) 2(2,0)
  silkscreen extent -3.66,-1.57 2.79,1.57, body extent -2.6,-1.3 2.6,1.3, height 2.42
SOIC-8 [mm] "duplicate of SO-8.  SOIC, 8-Leads, Body 5.0x4.0mm (max), Pitch 1.27mm, IPC Medium Density"
  oval 2.2x0.6 smd: 1(-2.4,1.905) 2(-2.4,0.635) 3(-2.4,-0.635) 4(-2.4,-1.905) 5(2.4,-1.905) 6(2.4,-0.635) 7(2.4,0.635) 8(2.4,1.905)
  silkscreen extent -0.9,-2.5 0.9,2.5, body extent -3,-2.45 3,2.45, height 1.63
SOT-323 [mm] "Zetex recommended land pattern.  March 2007"
  rect 0.8x0.6 smd: 1(-0.8,0.65) 2(-0.8,-0.65) 3(0.8,0)
  silkscreen extent -1.14,-1.22 0.77,1.22, body extent -1.13,-1.13 1.12,1.12, height 1.13
Sullins_PPPC031LFBN-RC [mm] "Sullins"
  rect 1.6x1.6 hole 1.016: 1(-2.54,0)
  round 1.6 hole 1.016: 2(0,0) 3(2.54,0)
  silkscreen extent -4.16,-1.37 4.16,1.9, body extent -4.16,-1.37 4.16,1.37, height 8.71
Sullins_PPPC102LFBN-RC [mil] "Sullins"
  rect 65x65 hole 40: 1(450,-50)
  round 65 hole 40: 2(450,50) 3(350,-50) 4(350,50) 5(250,-50) 6(250,50) 7(150,-50) 8(150,50) 9(50,-50) 10(50,50) 11(-50,-50) 12(-50,50) 13(-150,-50) 14(-150,50) 15(-250,-50) 16(-250,50) 17(-350,-50) 18(-350,50) 19(-450,-50) 20(-450,50)
  silkscreen extent -514,-116 526,104, body extent -514,-104 514,104, height 335
SW_B3U-1000P [mm] "OMRON"
  rect 0.8x1.7 smd: 1(-1.7,0) 2(1.7,0)
  silkscreen extent -1.5,-1.25 1.5,1.25, body extent -1.5,-1.25 1.5,1.25, height 1.75
SW_TDA04H0SB1 [mil] "C&K Components"
  rect 50x30 smd: 1(-150,75) 2(-150,25) 3(-150,-25) 4(-150,-75) 5(150,-75) 6(150,-25) 7(150,25) 8(150,75)
  silkscreen extent -126,-122 126,122, body extent -164,-122 163,122, height 91
TI_Stacked_Overlay_Small [mil]
  silkscreen extent -418,-98 418,98
TRANS_NexFET_Q3 [mm] "TI recommended land pattern (nominal) M0143-01"
  rect 0.63x0.5 smd mask+0.075: 1(-1.49,0.975) 2(-1.49,0.325) 3(-1.49,-0.325) 4(-1.49,-0.975) 5(1.38,-0.975) 6(1.38,-0.325) 7(1.38,0.325) 8(1.38,0.975)
  Top Layer region: -0.615,1.225 1.285,1.225 1.285,-1.225 -0.615,-1.225
  silkscreen extent -2.05,-2 2,2, body extent -1.76,-1.7 1.66,1.7, height 1.11
ZQZ0096A_Oval [mm] "BGA, 96-Leads, Body 6.0x6.0mm,  Pitch 0.50mm"
  round 0.275 smd: A1(-2.5,2.5) A11(2.5,2.5) B2(-2,2) B3(-1.5,2) B4(-1,2) B5(-0.5,2) B6(0,2) B7(0.5,2) B8(1,2) B9(1.5,2) B10(2,2) C2(-2,1.5) C10(2,1.5) D2(-2,1) D5(-0.5,1) D6(0,1) D7(0.5,1) D8(1,1) D10(2,1) E2(-2,0.5) E4(-1,0.5) E5(-0.5,0.5) E6(0,0.5) E7(0.5,0.5) E8(1,0.5) E10(2,0.5) F2(-2,0) F4(-1,0) F5(-0.5,0) F6(0,0) F7(0.5,0) F8(1,0) F10(2,0) G2(-2,-0.5) G4(-1,-0.5) G5(-0.5,-0.5) G6(0,-0.5) G7(0.5,-0.5) G8(1,-0.5) G10(2,-0.5) H2(-2,-1) H4(-1,-1) H5(-0.5,-1) H6(0,-1) H7(0.5,-1) H8(1,-1) H10(2,-1) J2(-2,-1.5) J10(2,-1.5) K2(-2,-2) K3(-1.5,-2) K4(-1,-2) K5(-0.5,-2) K6(0,-2) K7(0.5,-2) K8(1,-2) K9(1.5,-2) K10(2,-2) L1(-2.5,-2.5) L11(2.5,-2.5)
  oval 0.178x0.33 smd: A2(-2,2.5) A3(-1.5,2.5) A4(-1,2.5) A5(-0.5,2.5) A6(0,2.5) A7(0.5,2.5) A8(1,2.5) A9(1.5,2.5) A10(2,2.5) L2(-2,-2.5) L3(-1.5,-2.5) L4(-1,-2.5) L5(-0.5,-2.5) L6(0,-2.5) L7(0.5,-2.5) L8(1,-2.5) L9(1.5,-2.5) L10(2,-2.5)
  oval 0.33x0.178 smd: B1(-2.5,2) B11(2.5,2) C1(-2.5,1.5) C11(2.5,1.5) D1(-2.5,1) D11(2.5,1) E1(-2.5,0.5) E11(2.5,0.5) F1(-2.5,0) F11(2.5,0) G1(-2.5,-0.5) G11(2.5,-0.5) H1(-2.5,-1) H11(2.5,-1) J1(-2.5,-1.5) J11(2.5,-1.5) K1(-2.5,-2) K11(2.5,-2)
  silkscreen extent -3,-3 3,3, body extent -3.05,-3.05 3.05,3.05, height 1.01

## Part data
C1 C4: "CAP, CERM, 10 µF, 25 V, +/- 20%, X5R, 0603"
C2 C12: "CAP, CERM, 0.1 µF, 10 V, +/- 10%, X5R, 0201"
C3: "CAP, CERM, 0.22 µF, 6.3 V, +/- 20%, X5R, 0201"
C5: "CAP, CERM, 0.1 µF, 50 V, +/- 20%, C0G/NP0, 0402"
C6: "CAP, CERM, 1 µF, 35 V, +/- 10%, JB, 0402"
C7 C8 C9 C10: "CAP, CERM, 0.01 µF, 50 V, +/- 10%, X7R, 0402"
C11: "CAP, CERM, 22 µF, 10 V, +/- 20%, X5R, 0603"
C13 C16 C17 C18: "CAP, CERM, 1 µF, 10 V, +/- 20%, X5R, 0201"
C14: "CAP, CERM, 10 µF, 10 V, +/- 20%, X5R, 0402"
C15 C19: "CAP, CERM, 220 pF, 25 V, +/- 10%, X7R, 0201"
C20 C23 C26 C31 C34 C37 C42 C45 C48: "CAP, CERM, 0.1uF, 50V, +/-20%, C0G/NP0, 0402"
C22 C33 C44: "CAP, CERM, 10 µF, 25 V, +/- 10%, X5R, 0805"
C24 C25 C35 C36 C46 C47: "CAP, CERM, 22 µF, 35 V, +/- 20%, X5R, 0805"
C27 C30 C38 C41 C49 C52: "CAP, CERM, 120 pF, 50 V, +/- 5%, C0G/NP0, 0402"
C28: "CAP, CERM, 330 pF, 50 V, +/- 5%, C0G/NP0, 0402"
C29: "CAP, CERM, 5600 pF, 50 V, +/- 10%, X7R, 0402"
C39: "CAP, CERM, 100 pF, 50 V, +/- 10%, X7R, 0402"
C40: "CAP, CERM, 2200 pF, 50 V, +/- 10%, X5R, 0402"
C50: "CAP, CERM, 91 pF, 50 V, +/- 5%, C0G/NP0, 0402"
C51: "CAP, CERM, 1800 pF, 50 V, +/- 10%, X7R, 0402"
C53: "CAP, CERM, 0.01 µF, 10 V, +/- 10%, X5R, 0201"
D1: "Diode, Schottky, 40 V, 3 A, SMA"
D2 D3 D4 D5 D6 D7 D8 D9: "LED, White, SMD"
FID1 FID2 FID3 FID4 FID5 FID6: "Fiducial mark.  There is nothing to buy or mount."
H1 H2 H3 H4: "Machine Screw, Round, #4-40 x 1/4, Nylon, Philips panhead"
H5 H6 H7 H8: "Standoff, Hex, 0.5\"L #4-40 Nylon"
J1: "Connector, Receptacle, USB Type C, R/A, SMT"
J2 J3: "Receptacle, 100mil, 10x2, Gold, TH"
J4: "Connector,  DC Power Jack, R/A, 3 Pos, TH"
J5: "Receptacle, 100mil, 3x1, Gold, TH"
J6: "Header, 100mil, 2x1, Tin, TH"
J7: "Header, 100mil, 2x2, Tin, SMT"
L1: "Ferrite Bead, 21 ohm @ 100MHz, 6A, 0805"
Logo1: library part TI_Logo, "Texas Instrument Corporate Signature"
Logo2: library part Pb-Free
Logo3: library part FCC_disclaimer, "FCC_disclaimer"
Q1 Q2: "MOSFET, N-CH, 30 V, 60 A, SON 3.3x3.3mm"
Q3 Q4 Q5 Q6 Q7 Q8 Q9 Q10: library part "DTC114EUAT106, Rohm", "Transistor, NPN, 50 V, 0.05 A, SOT-323"
R1: "RES, 0.01 ohm, 1%, 0.25W, 0805"
R2 R3 R5 R6 R10 R11 R16 R17 R18 R19 R22 R23 R30 R31 R32 R34 R35 R36 R37 R38 R39 R40 R41 R46 R47 R48 R50 R51 R53 R54 R56 R57 R58 R59 R60 R61 R62 R63 R64 R65 R66 R67 R68 R69 R71: "RES, 0, 5%, 0.05 W, 0201"
R4 R7 R8 R9: "RES, 3.3 k, 5%, 0.063 W, 0402"
R12 R13 R14 R15 R27 R42 R43 R44 R45: "RES, 1.00 k, 1%, 0.05 W, 0201"
R20 R75 R76 R79 R80: "RES, 3.83 k, 1%, 0.05 W, 0201"
R21 R24 R25 R26 R29 R33 R49 R52 R55 R70: "RES, 100 k, 1%, 0.05 W, 0201"
R28: "RES, 15.0 k, 1%, 0.063 W, 0402"
R72 R73 R74 R86 R87 R89 R90 R96: "RES, 560, 5%, 0.063 W, 0402"
R77 R78: "RES, 9.09 k, 1%, 0.05 W, 0201"
R81 R91 R101: "RES, 220 k, 5%, 0.063 W, 0402"
R82 R92 R102: "RES, 100 k, 1%, 0.063 W, 0402"
R83 R93 R103: "RES, 43.2 k, 1%, 0.063 W, 0402"
R84: "RES, 32.4 k, 1%, 0.063 W, 0402"
R85: "RES, 2.74 k, 1%, 0.063 W, 0402"
R88 R97 R109: "RES, 47.5 k, 1%, 0.063 W, 0402"
R94: "RES, 19.1 k, 1%, 0.063 W, 0402"
R95: "RES, 8.45 k, 1%, 0.063 W, 0402"
R104: "RES, 7.15 k, 1%, 0.063 W, 0402"
R108: "RES, 9.53 k, 1%, 0.063 W, 0402"
S1 S2: "DIP Switch, SPST 4Pos, Slide, SMT"
S3: "SWITCH TACTILE SPST-NO 0.05A 12V"
TP1 TP2 TP3 TP4 TP5: library part 5019, "Test Point, Miniature, SMT"
U1: "3V, 8Mbit, Serial Flash Memory with Dual and Qual SPI, SOIC-8"
U2: "TPS65982 Preview Specification, ZQZ0096A"
U3 U4: "1, 4, 6 CHANNEL PROTECTION SOLUTION FOR SUPER-SPEED (UP TO 6 GBPS) INTERFACE, DQA0010A"
U5 U6 U7: "4.5V to 28V Input, 3A Output, Synchronous SWIFT Step-Down DC-DC Converter, DRC0010J"
ZZ2 ZZ3 ZZ4: library part AssemblyNote

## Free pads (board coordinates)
  round 75 hole 52: 0(1147,1792)

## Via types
v1: diameter 16, hole 8, Top Layer to Bottom Layer, tented both sides, 166 vias
v2: diameter 16, hole 8.1, Top Layer to Bottom Layer, tented both sides, 54 vias
v3: diameter 20, hole 10, Top Layer to Bottom Layer, tented both sides, 41 vias
v4: diameter 19.68, hole 7.87, Top Layer to Bottom Layer, 12 vias

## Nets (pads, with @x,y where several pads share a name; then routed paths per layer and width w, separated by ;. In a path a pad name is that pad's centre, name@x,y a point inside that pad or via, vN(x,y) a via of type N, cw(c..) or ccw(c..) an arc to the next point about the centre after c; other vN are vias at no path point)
3V3_VSENSE: C27.2 R82.1 R84.2 U5.6 | length 222.7
  Bottom Layer w10: U5.6@545.37,650.88 558.88,650.88 580,629.76 580,577.38 R84.2@605,552.38 617.62,565 647.38,565 R82.1@650.38,565 C27.2@650.38,524
5V_VSENSE: C38.2 R92.1 R94.2 U6.6 | length 231.3
  Bottom Layer w10: U6.6@1506.97,1252.88 1506.97,1242.63 1524.6,1225 1524.6,1169 1552.6,1141 R94.2@1552.6,1137.38 1599.35,1137.38 C38.2@1602.98,1141 R92.1@1602.98,1186
12V_VSENSE: C49.2 R102.1 R104.2 U7.6 | length 236.7
  Bottom Layer w10: C49.2@399.12,1299.31 436.12,1299.31 436.12,1353.06 408.12,1381.06 408.12,1416.69 424.75,1433.32 U7.6@472,1433.32
AUX_N: R34.2 U2.J2 | length 720.6
  Top Layer w5: R34.2@322.96,999 v1(348,999) ; v1(756,859) 771,874 853.85,874 859.66,879.82 883,879.82 ; 883,880.32 911.26,880.32 U2.J2@921.26,890.32
  MidLayer1 w4.4: v1(348,999) 348,1026.1 364,1042.1 507.44,1042.1 683.49,866.05 748.95,866.05 v1(756,859)
AUX_P: R31.2 U2.J1 | length 693.9
  Top Layer w5: R31.2@323.96,1099 v1(348,1099) ; v1(756,884) 756.5,884.5 849.5,884.5 855.82,890.82 883,890.82 ; 882,890.32 U2.J1@901.57,890.32
  MidLayer1 w4.4: v1(348,1099) 348,1069 364,1053 511.95,1053 688,876.95 748.95,876.95 v1(756,884)
BUSPOWERZ: R49.1 S2.3 S2.4 U2.F10 | length 2459.4
  Top Layer w4: U2.F10@1078.74,949.37 1088.94,939.17 1242.17,939.17 1477,1174 1756,1174 1775,1193 1825,1193 1850,1168 1850,1128 1879,1099 1927,1099 1954.33,1126.33 1954.33,1474.67 1932,1497 1643,1497 1620,1474 1528,1474 1496,1506 1496,1638 1388,1746 1310,1746 1300,1756 S2.4@1300,1781
  Top Layer w8: S2.4@1300,1781 S2.3@1300,1831
  Top Layer w10: S2.4@1313,1782 1347,1782 ; 1348,1782 1347,1782 ; v1(1386,1821) 1347,1782
  Bottom Layer w10: R49.1@1386,1800.96 v1(1386,1821)
C_CC1: C15.1 J1.A5 R10.2 TP1.1 U2.L9 U4.2 U4.9 | length 1273.6
  Top Layer w8: J1.A5@973.11,305.31 973,305.42 973,382 1006,415 1169.1,415 1194.55,440.45 ; U2.L9@1061,849 1096,814 1117,814 1138,793 C15.1@1138,761 1138,726 1219.69,644.31 U4.2@1219.69,529.1 U4.9@1219.69,495.64 1219.69,465.58 1194.55,440.45 ; TP1.1@1550.5,569.5 1550.5,523.5 1446,419 1216,419 1194.55,440.45
C_CC2: C19.1 J1.B5 R11.2 TP2.1 U2.L10 U4.1 U4.10 | length 964.3
  Top Layer w8: U2.L10@1078.74,850.94 1100.89,828.8 1137.24,828.8 R11.2@1177.04,789 1177.04,762.97 C19.1@1179.01,761 1179.01,745.99 1239.37,685.63 U4.1@1239.37,529.1 U4.10@1239.37,495.64 v1@1239.37,458.63 ; v1(1241,457) v1@1239.37,458.63 ; 1302.96,468 1293.59,458.63 v1@1239.37,458.63 ; 1303,468 1377,542 TP2.1@1377,562
  MidLayer1 w8: v1(1029,263) 1048,263 v1@1239.37,454.37
C_SBU_N: J1.B8 U2.L8 U4.4 U4.7 | length 840.3
  Top Layer w4: 1039.37,837.63 U2.L8@1039.37,850.94
  Top Layer w4.8: v1(947,383) 1001.6,437.6 1155.6,437.6 1176,458 1176,473 1180.32,477.32 U4.7@1180.32,495.64
  Top Layer w5: 1040.08,837.63 1056,821.71 1056,748.5 1175.72,628.78 1175.72,550.59 1180.32,546 U4.4@1180.32,529.1 U4.7@1180.32,495.64
  MidLayer1 w4.4: v1(947,383) 965,365 v1(965,263)
C_SBU_P: J1.A8 U2.K8 U4.5 U4.6 | length 892.4
  Top Layer w4: 1030,837 1030,861.26 U2.K8@1039.37,870.63
  Top Layer w4.4: J1.A8@1032.17,305.31 1032.3,305.44 1034,307.15 v1(1034,331)
  Top Layer w5: v1(947,446) 949,448 1151.29,448 1165.6,462.31 1165.6,473 1160.63,477.97 U4.6@1160.63,495.64 U4.5@1160.63,529.1 1160.63,546 1165.22,550.59 1165.22,624.43 1045.5,744.15 1045.5,817.36 1029.37,833.49 1029.37,837.63 ; J1.A8@1032.17,305.31 1032.17,306.26 J1.A8@1032.17,321.83
  MidLayer1 w4.4: v1(947,446) 1034,359 v1(1034,331)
